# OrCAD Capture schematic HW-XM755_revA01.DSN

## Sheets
1 00_TITLE: title: HW-XM755; rev: A01; note: 038-05099-01
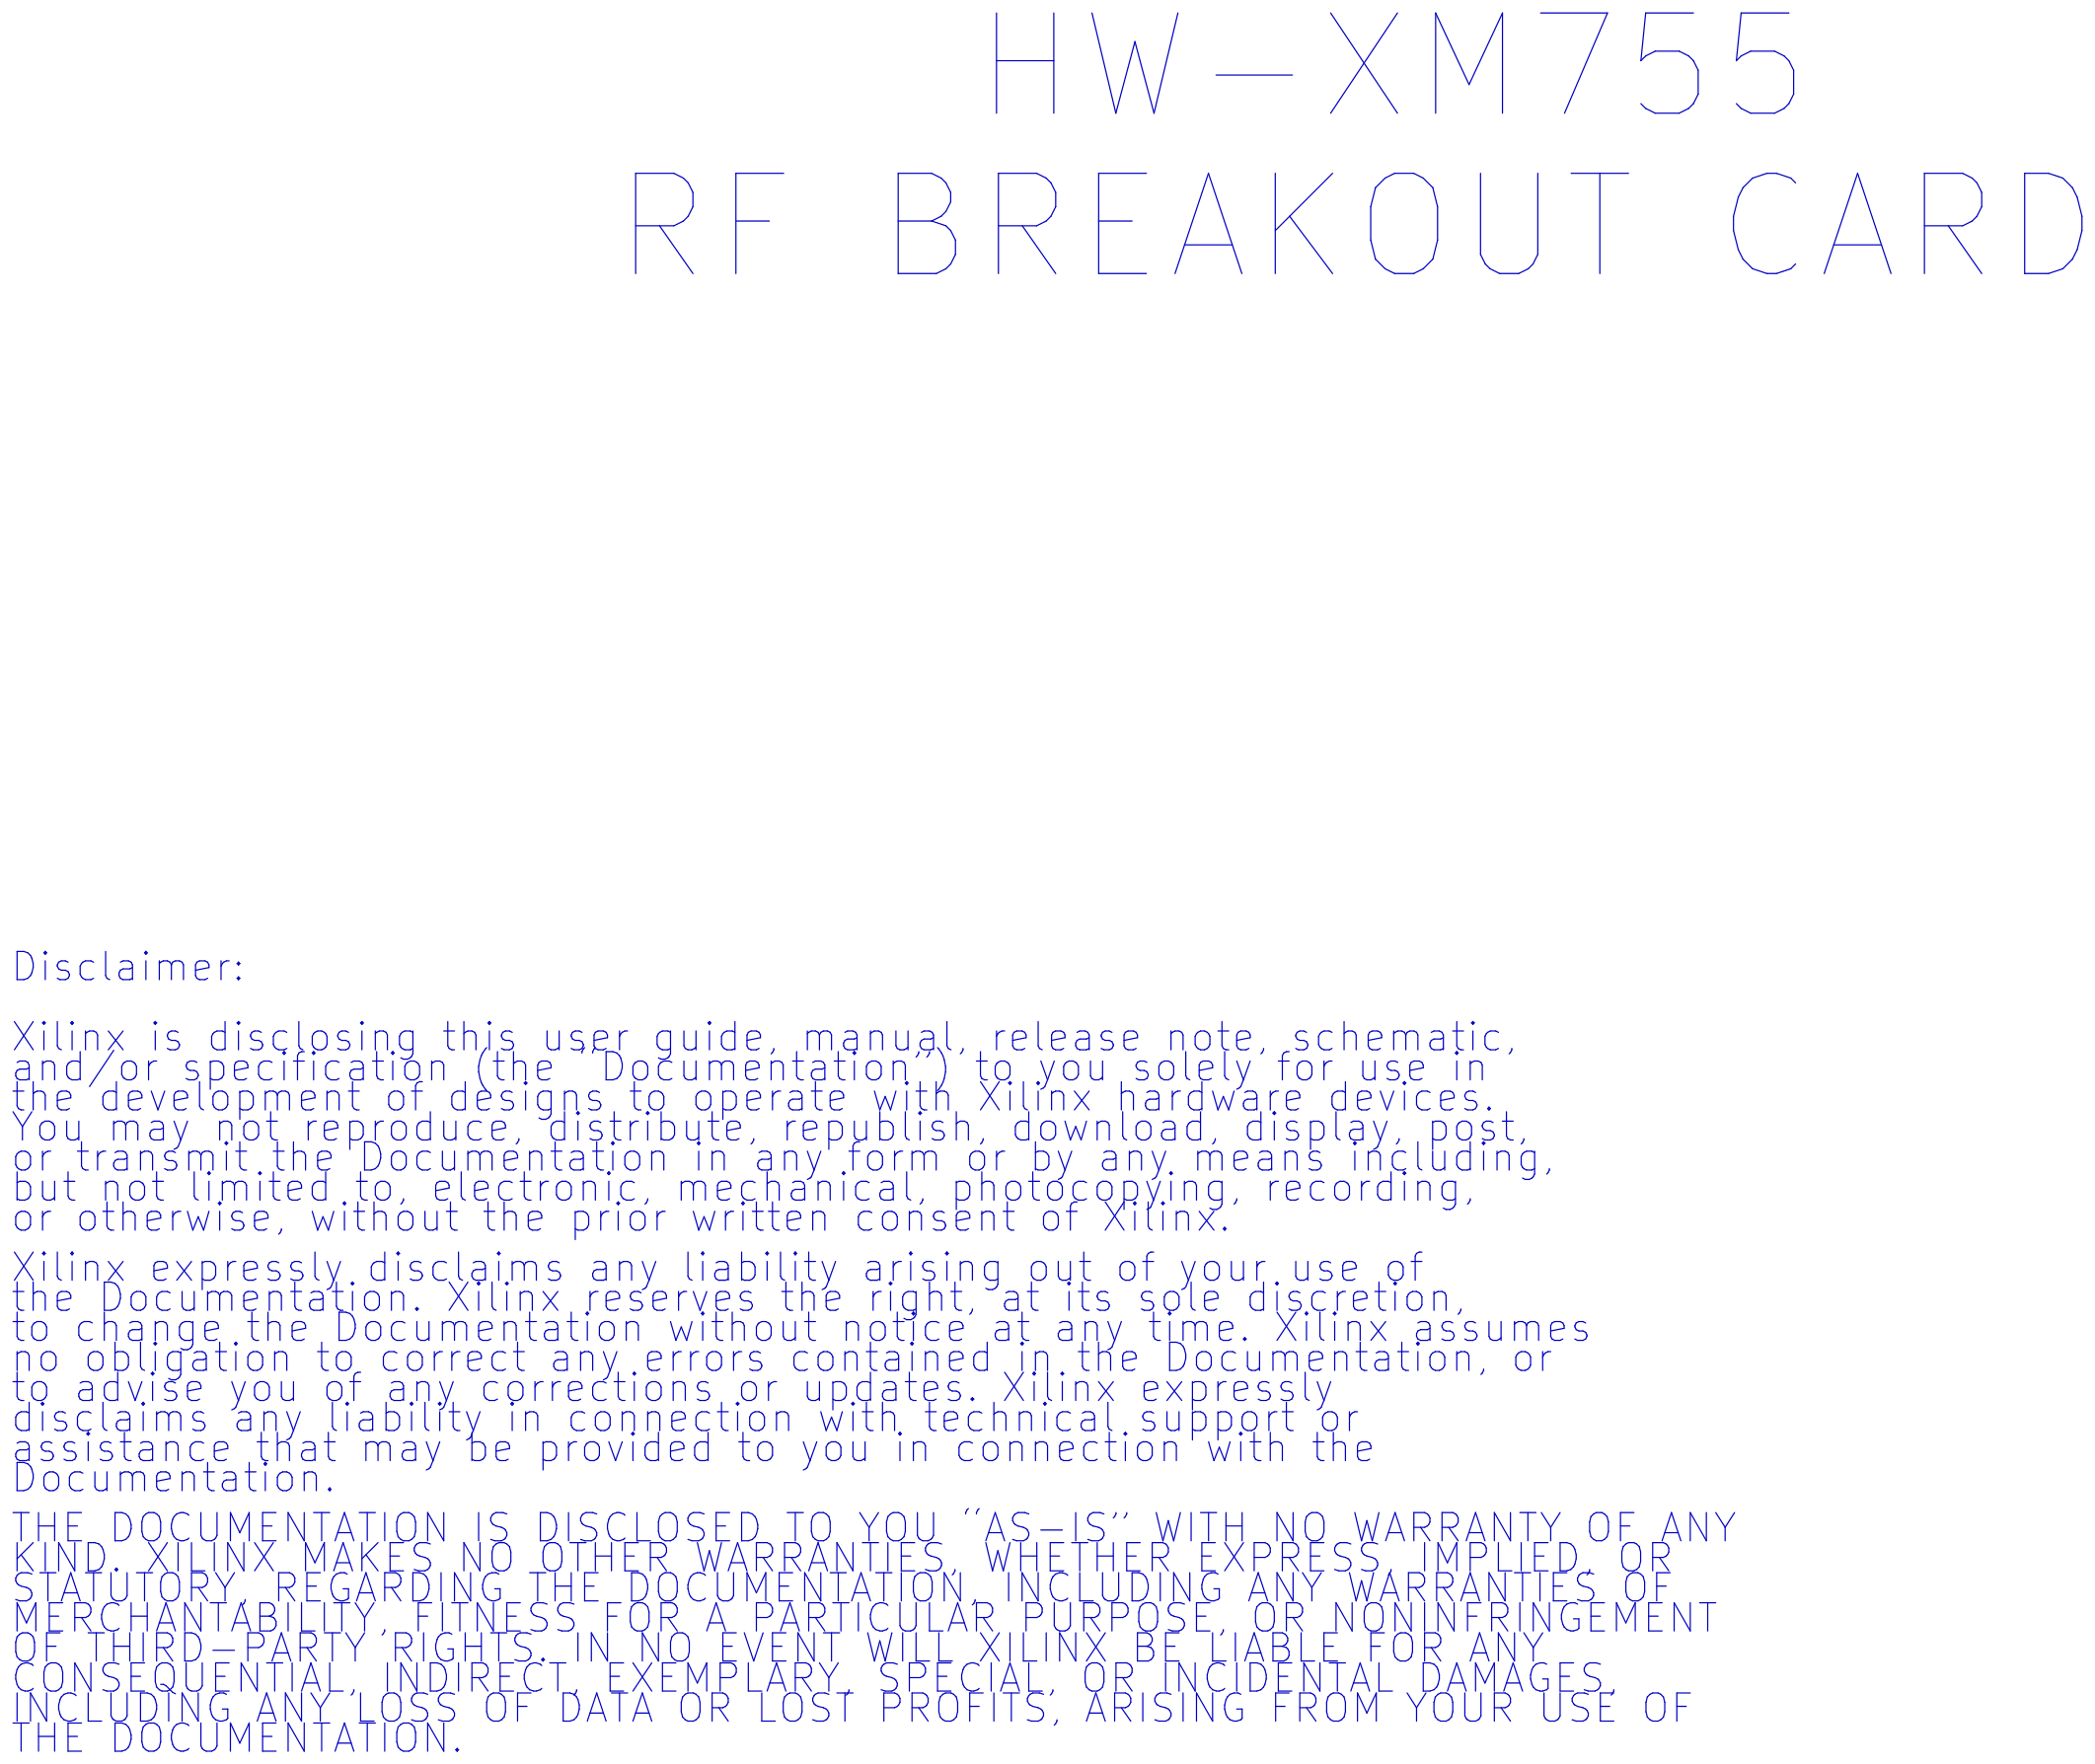
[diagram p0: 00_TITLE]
2 01_Block_Diagram
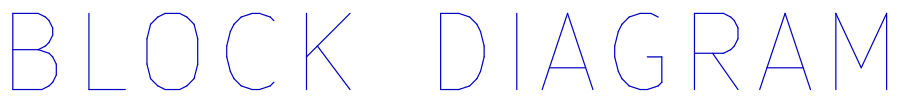
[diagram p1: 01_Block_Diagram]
3 02_Balun_ADC: size D
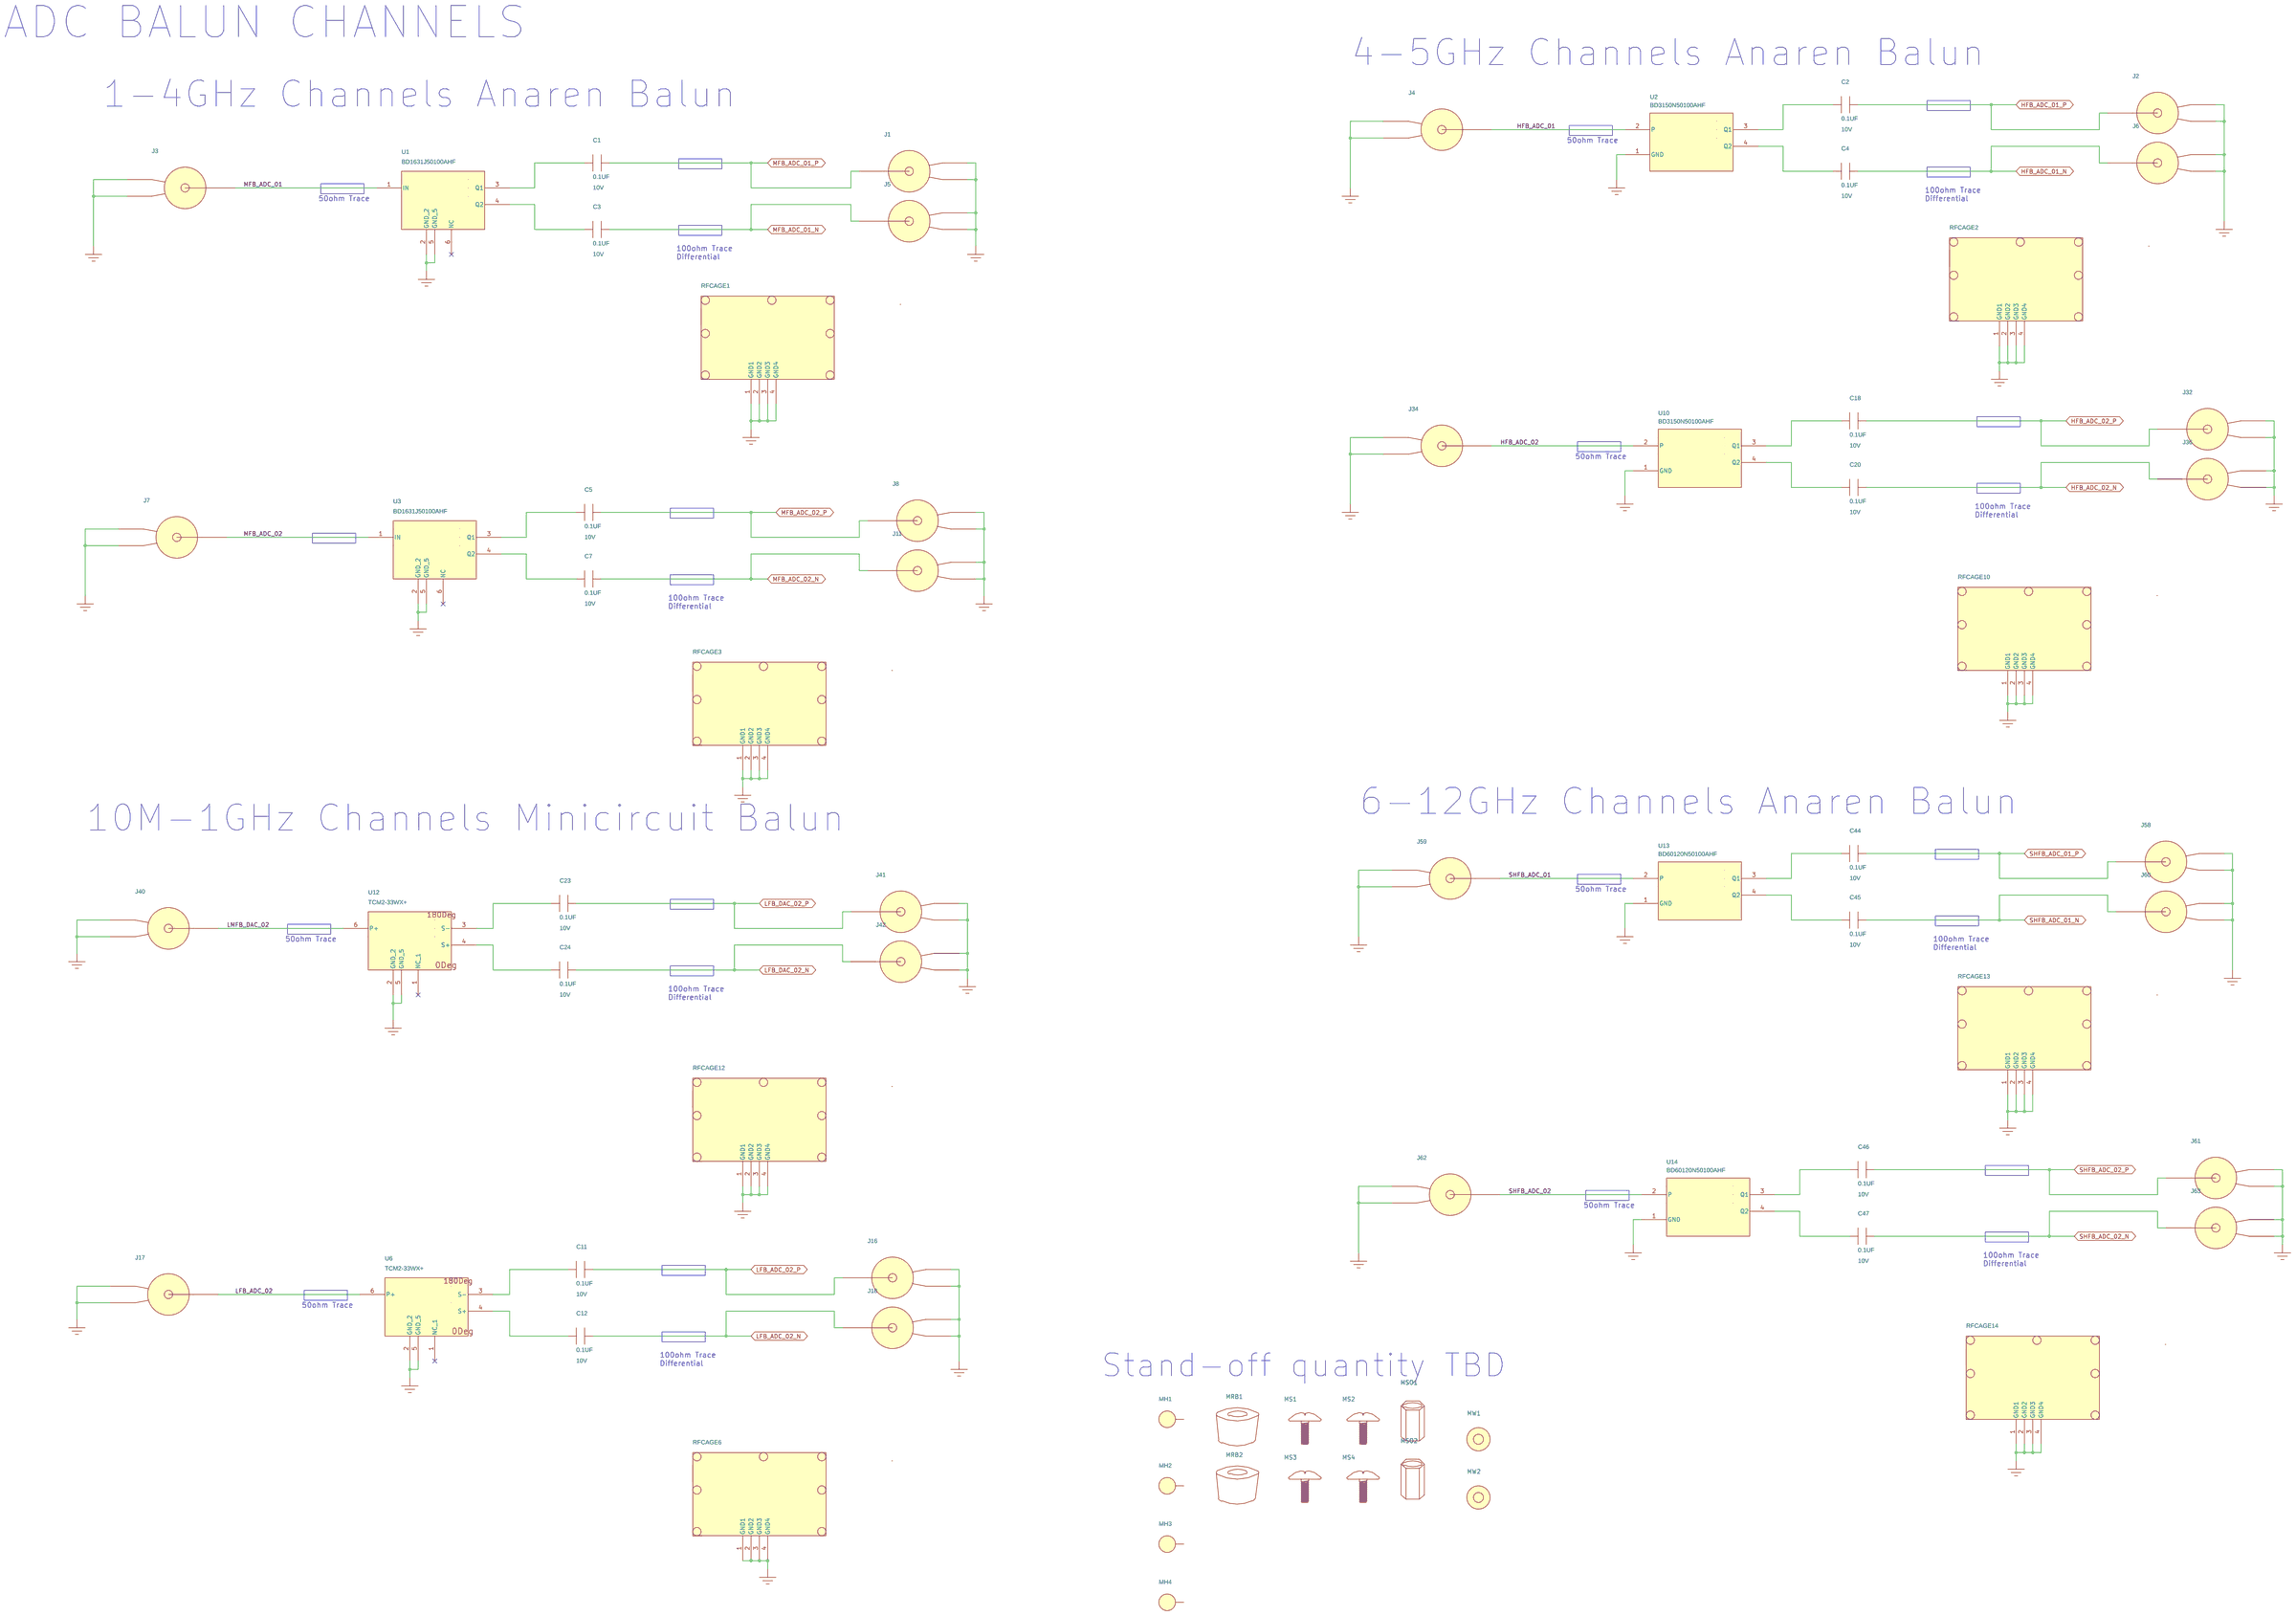
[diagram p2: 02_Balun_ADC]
4 03_SMAs_ADC: size Custom
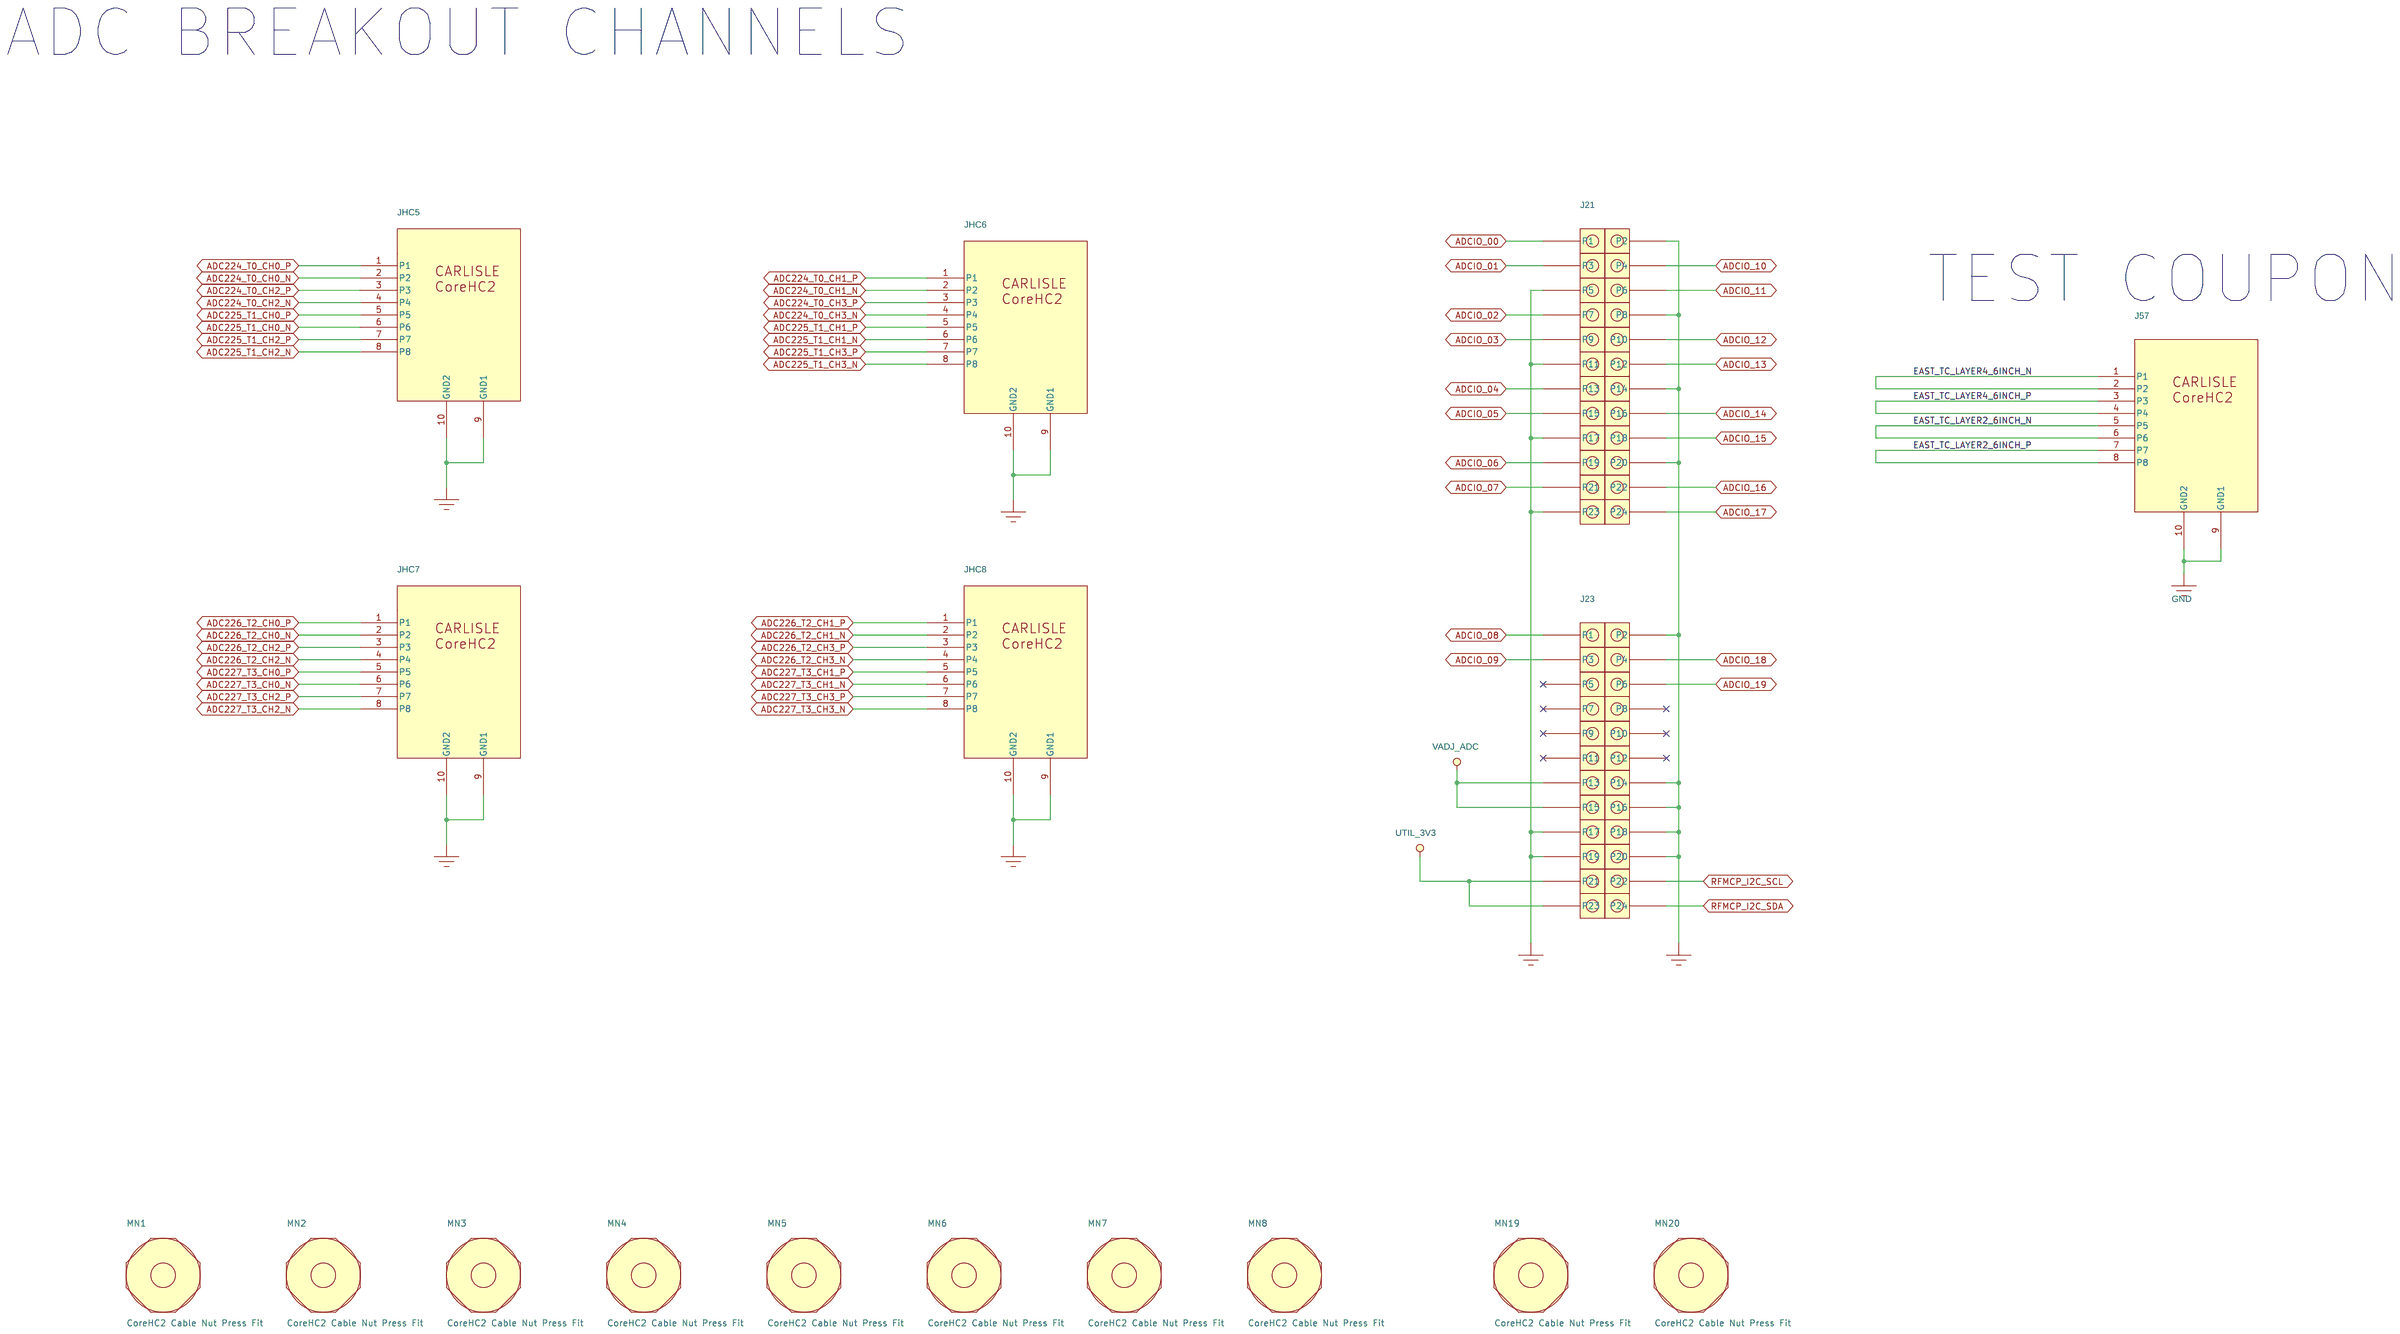
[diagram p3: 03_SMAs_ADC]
5 04_Balun_DAC: size D
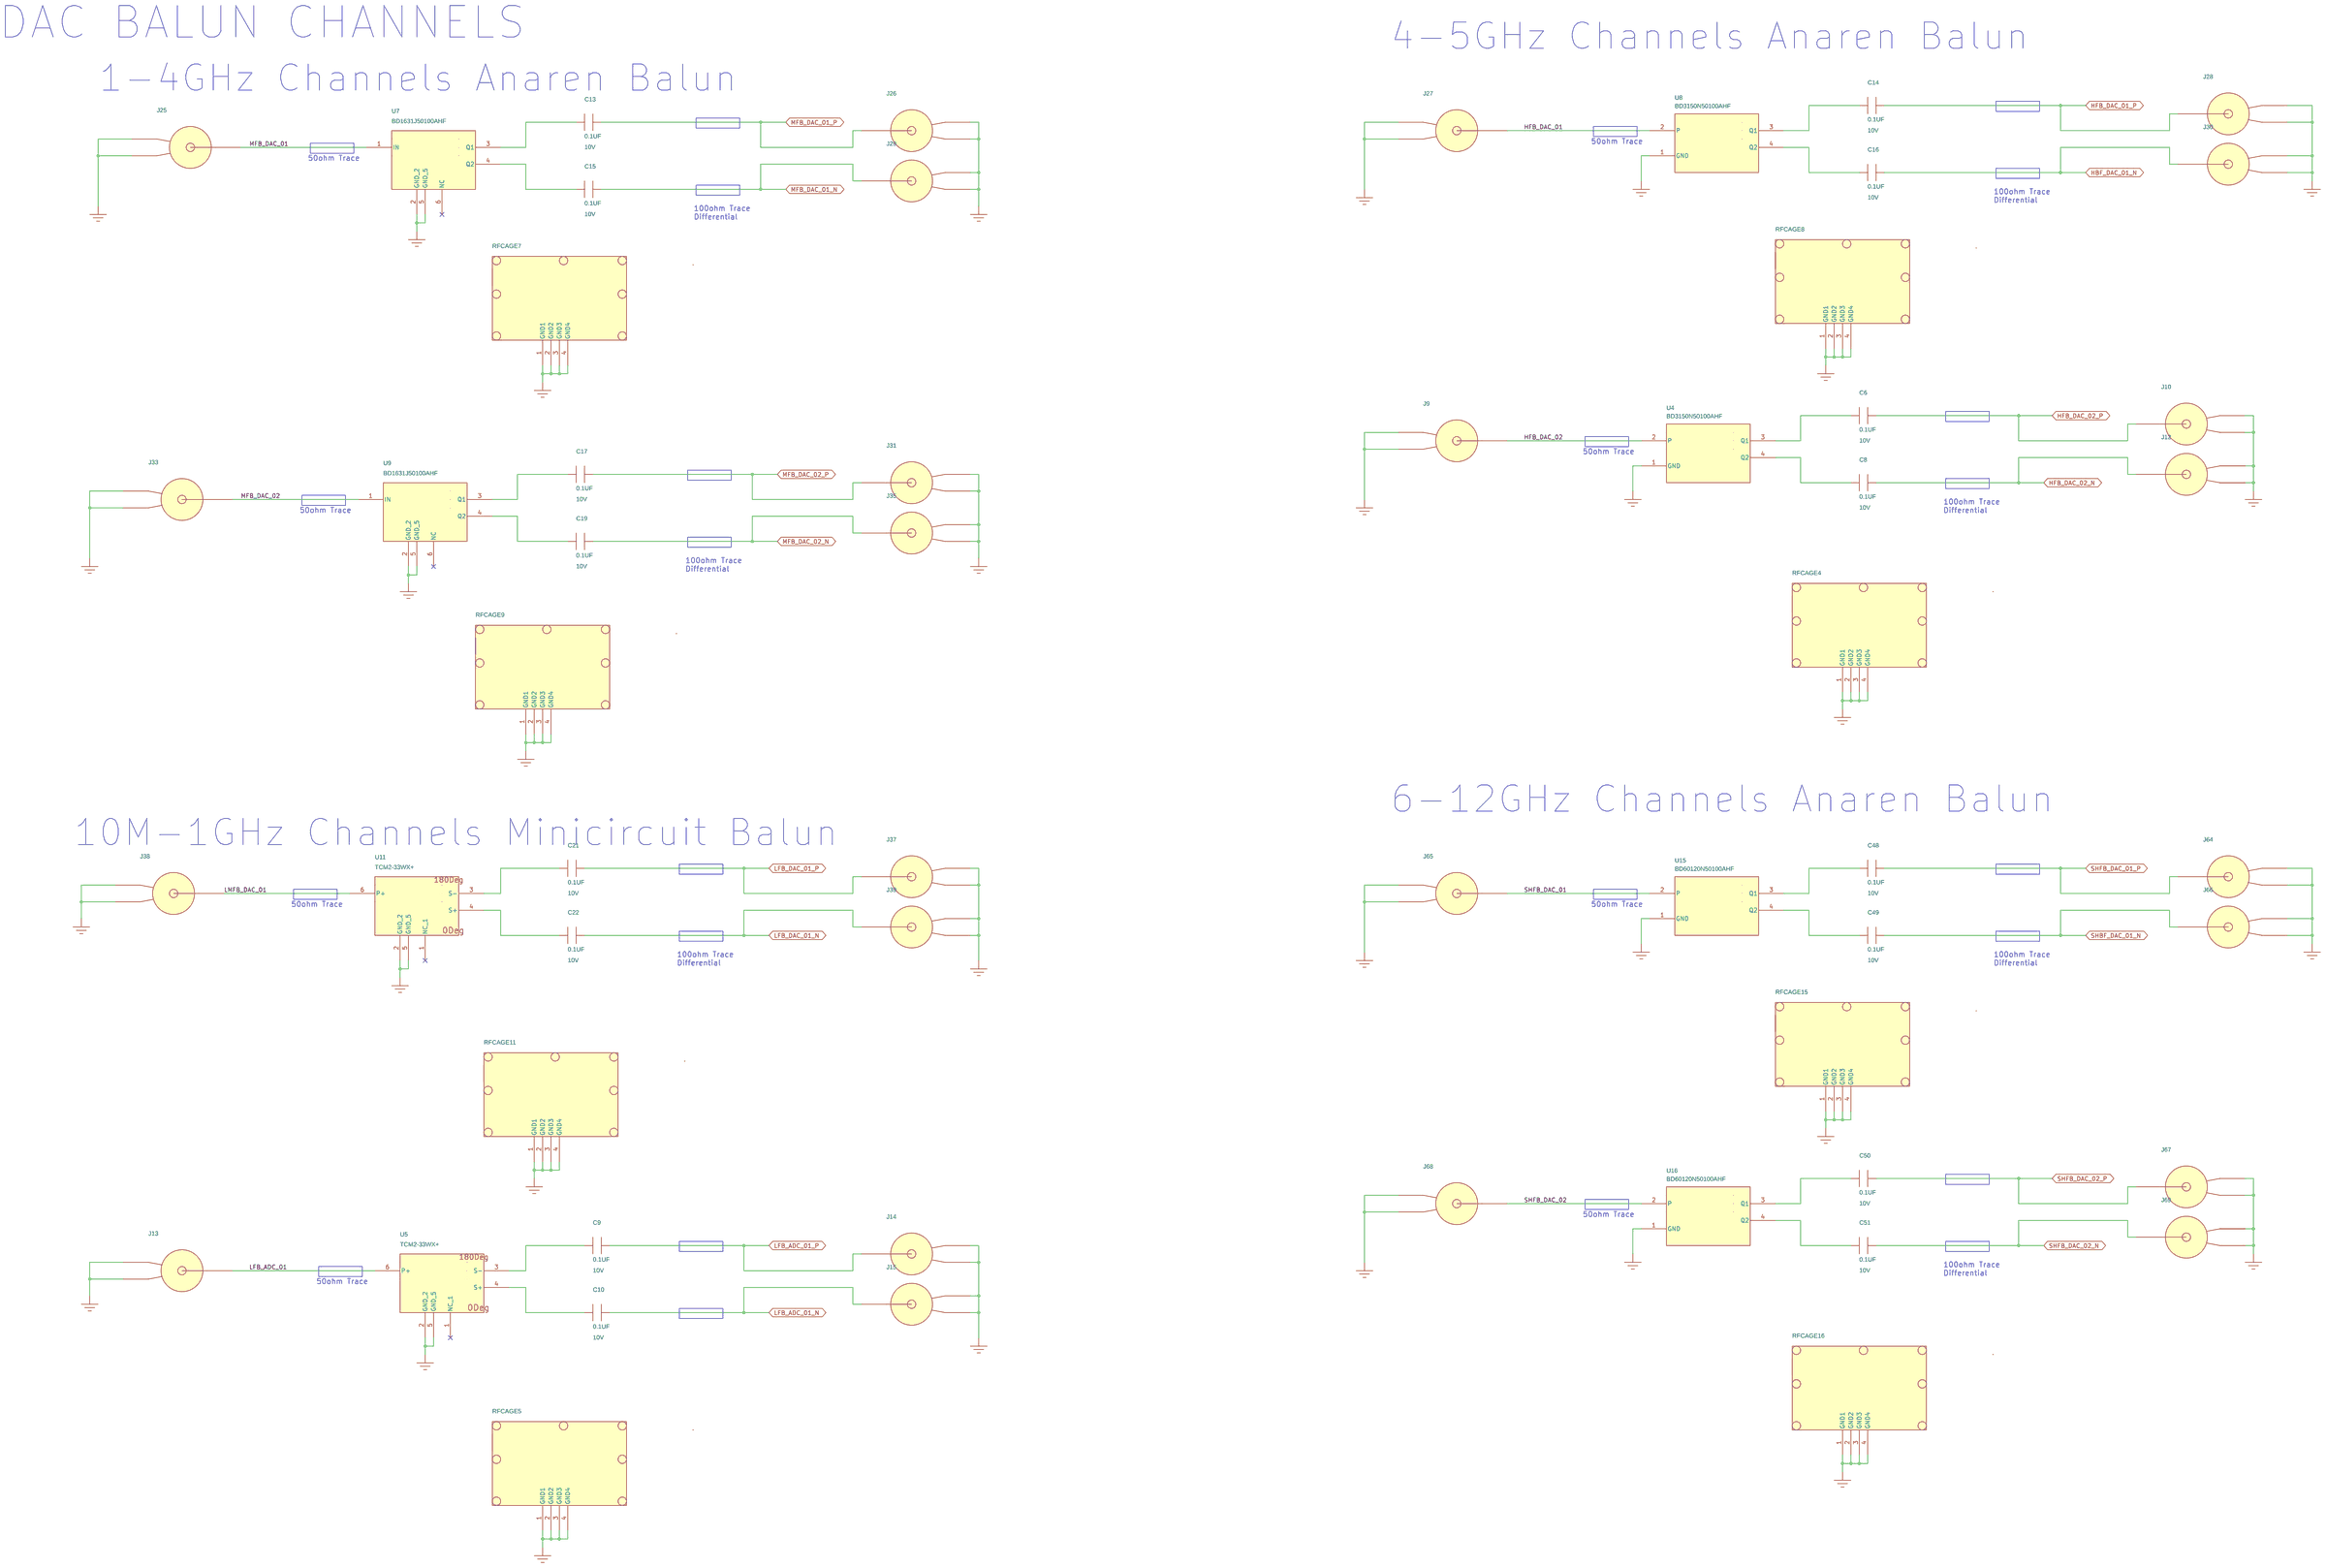
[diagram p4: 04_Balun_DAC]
6 05_SMAs_DAC: size Custom
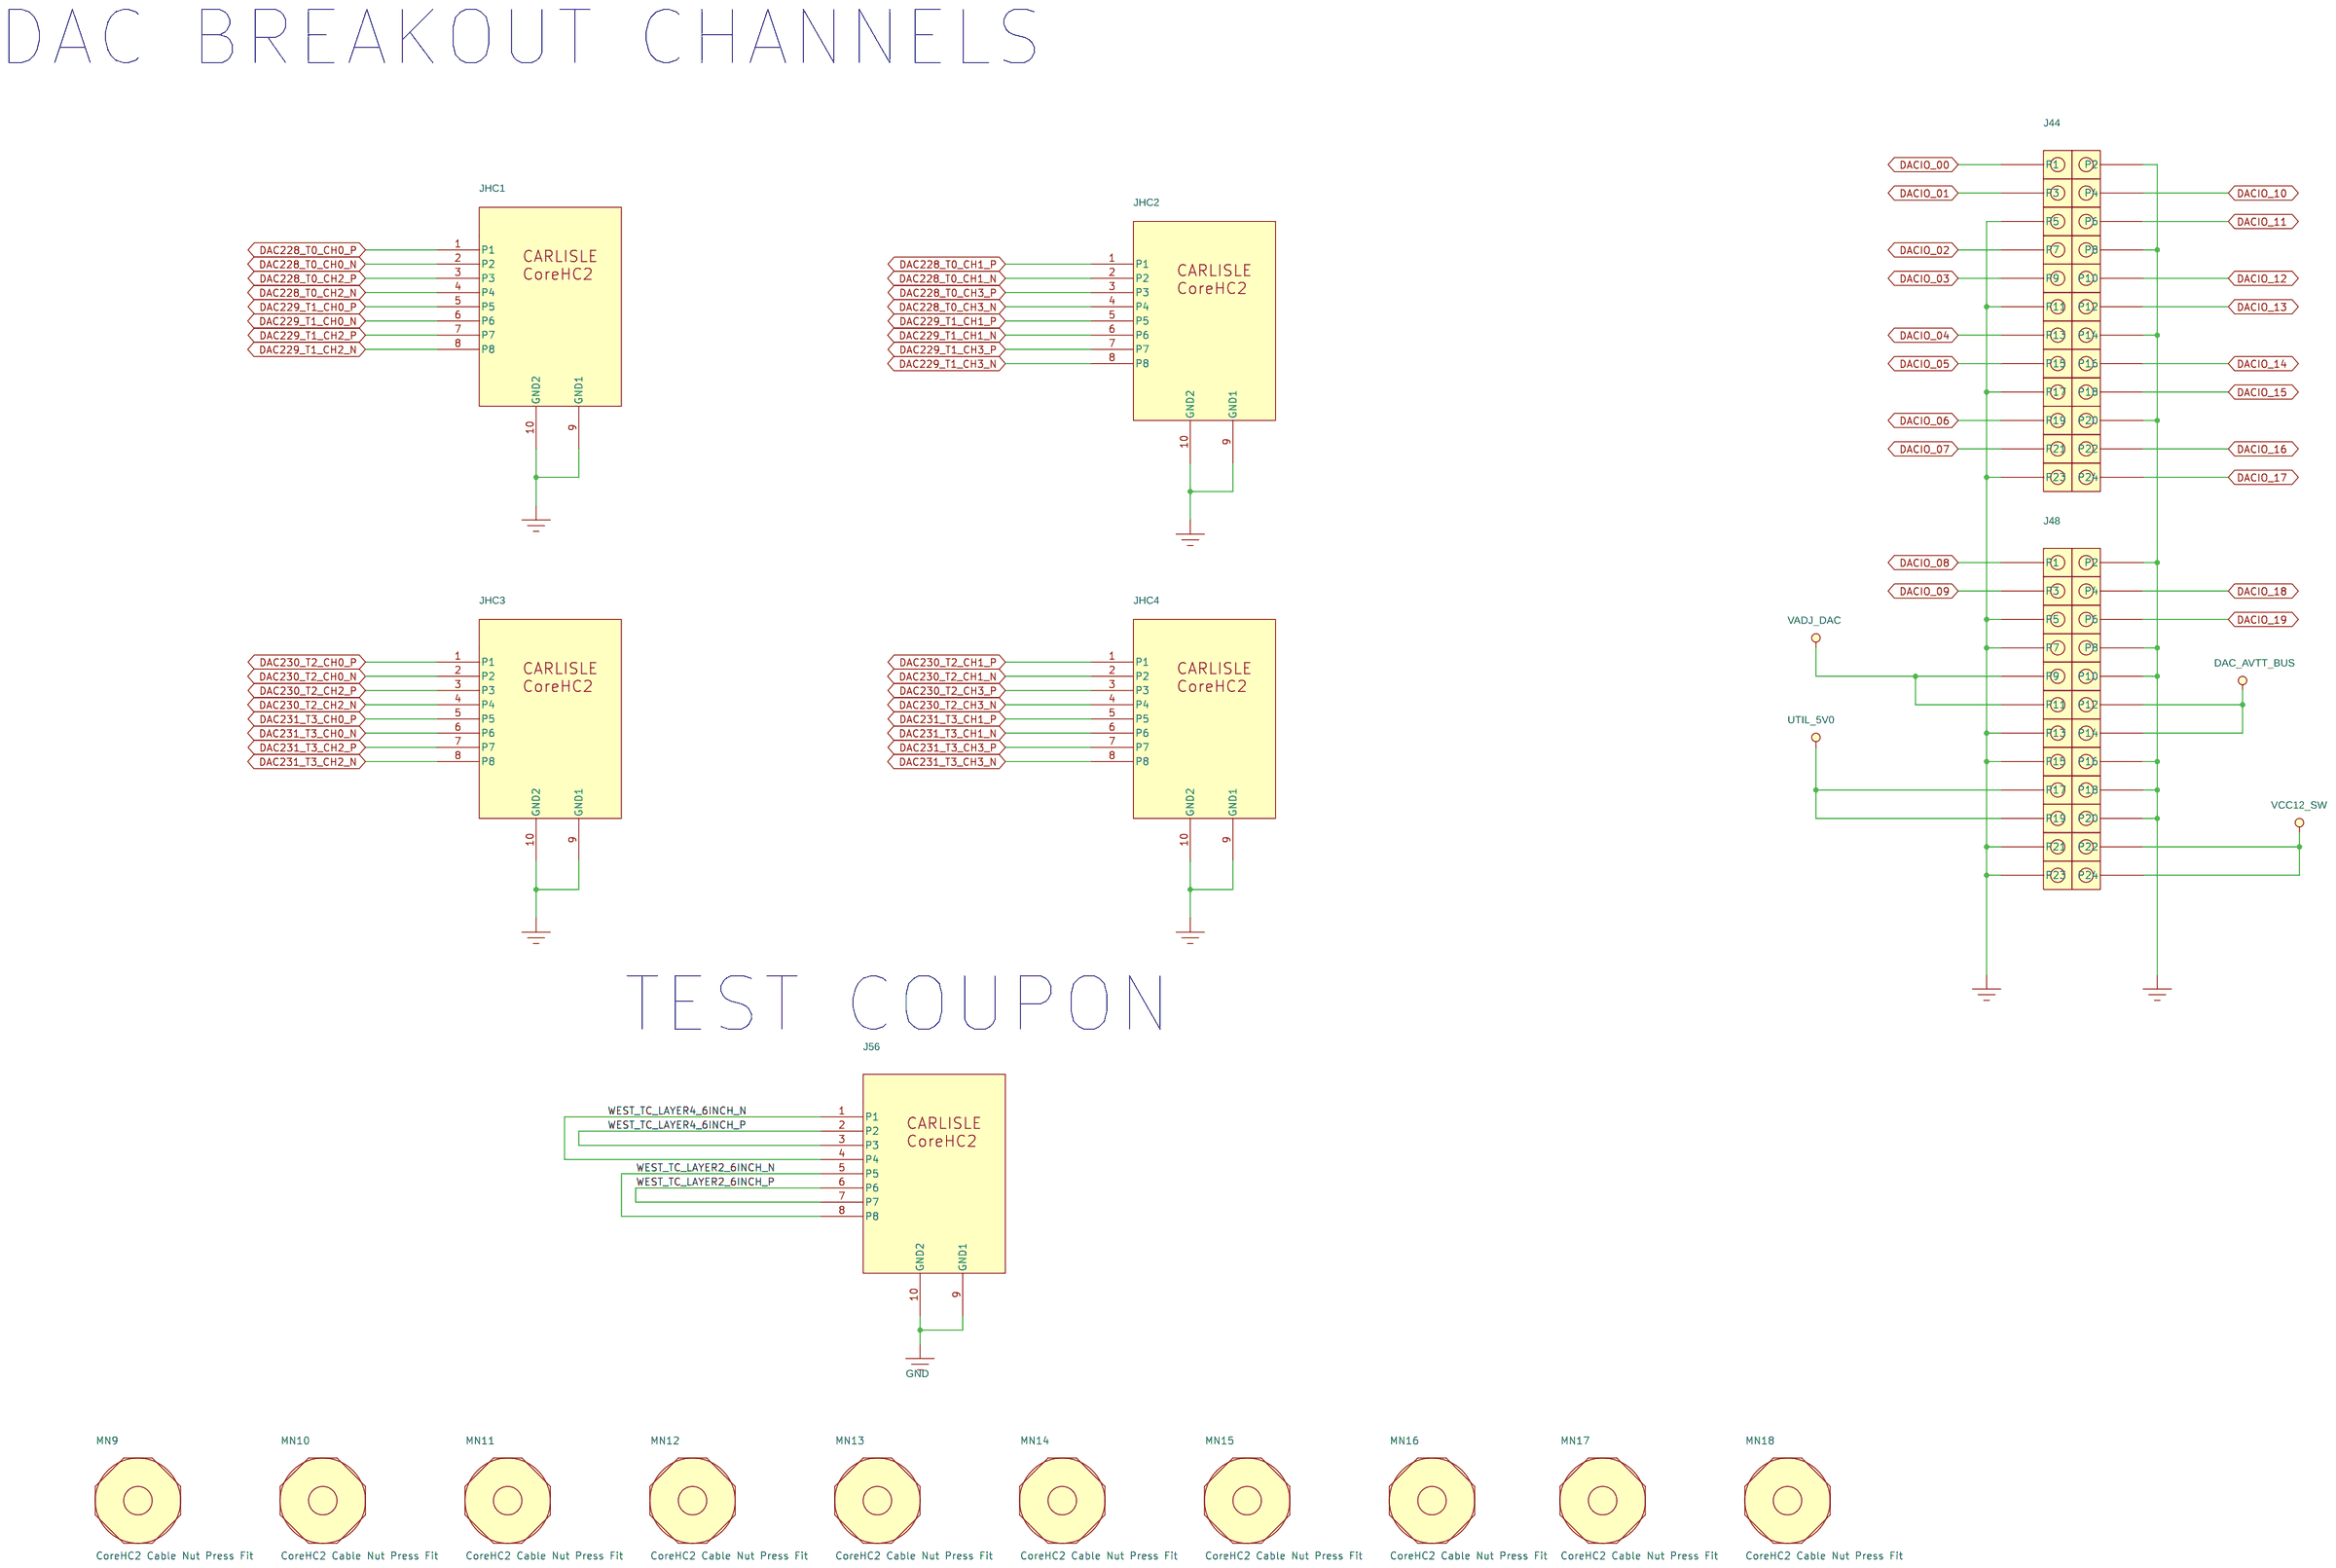
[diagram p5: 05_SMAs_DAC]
7 06_RFMC+_Connector_ADC: size Custom
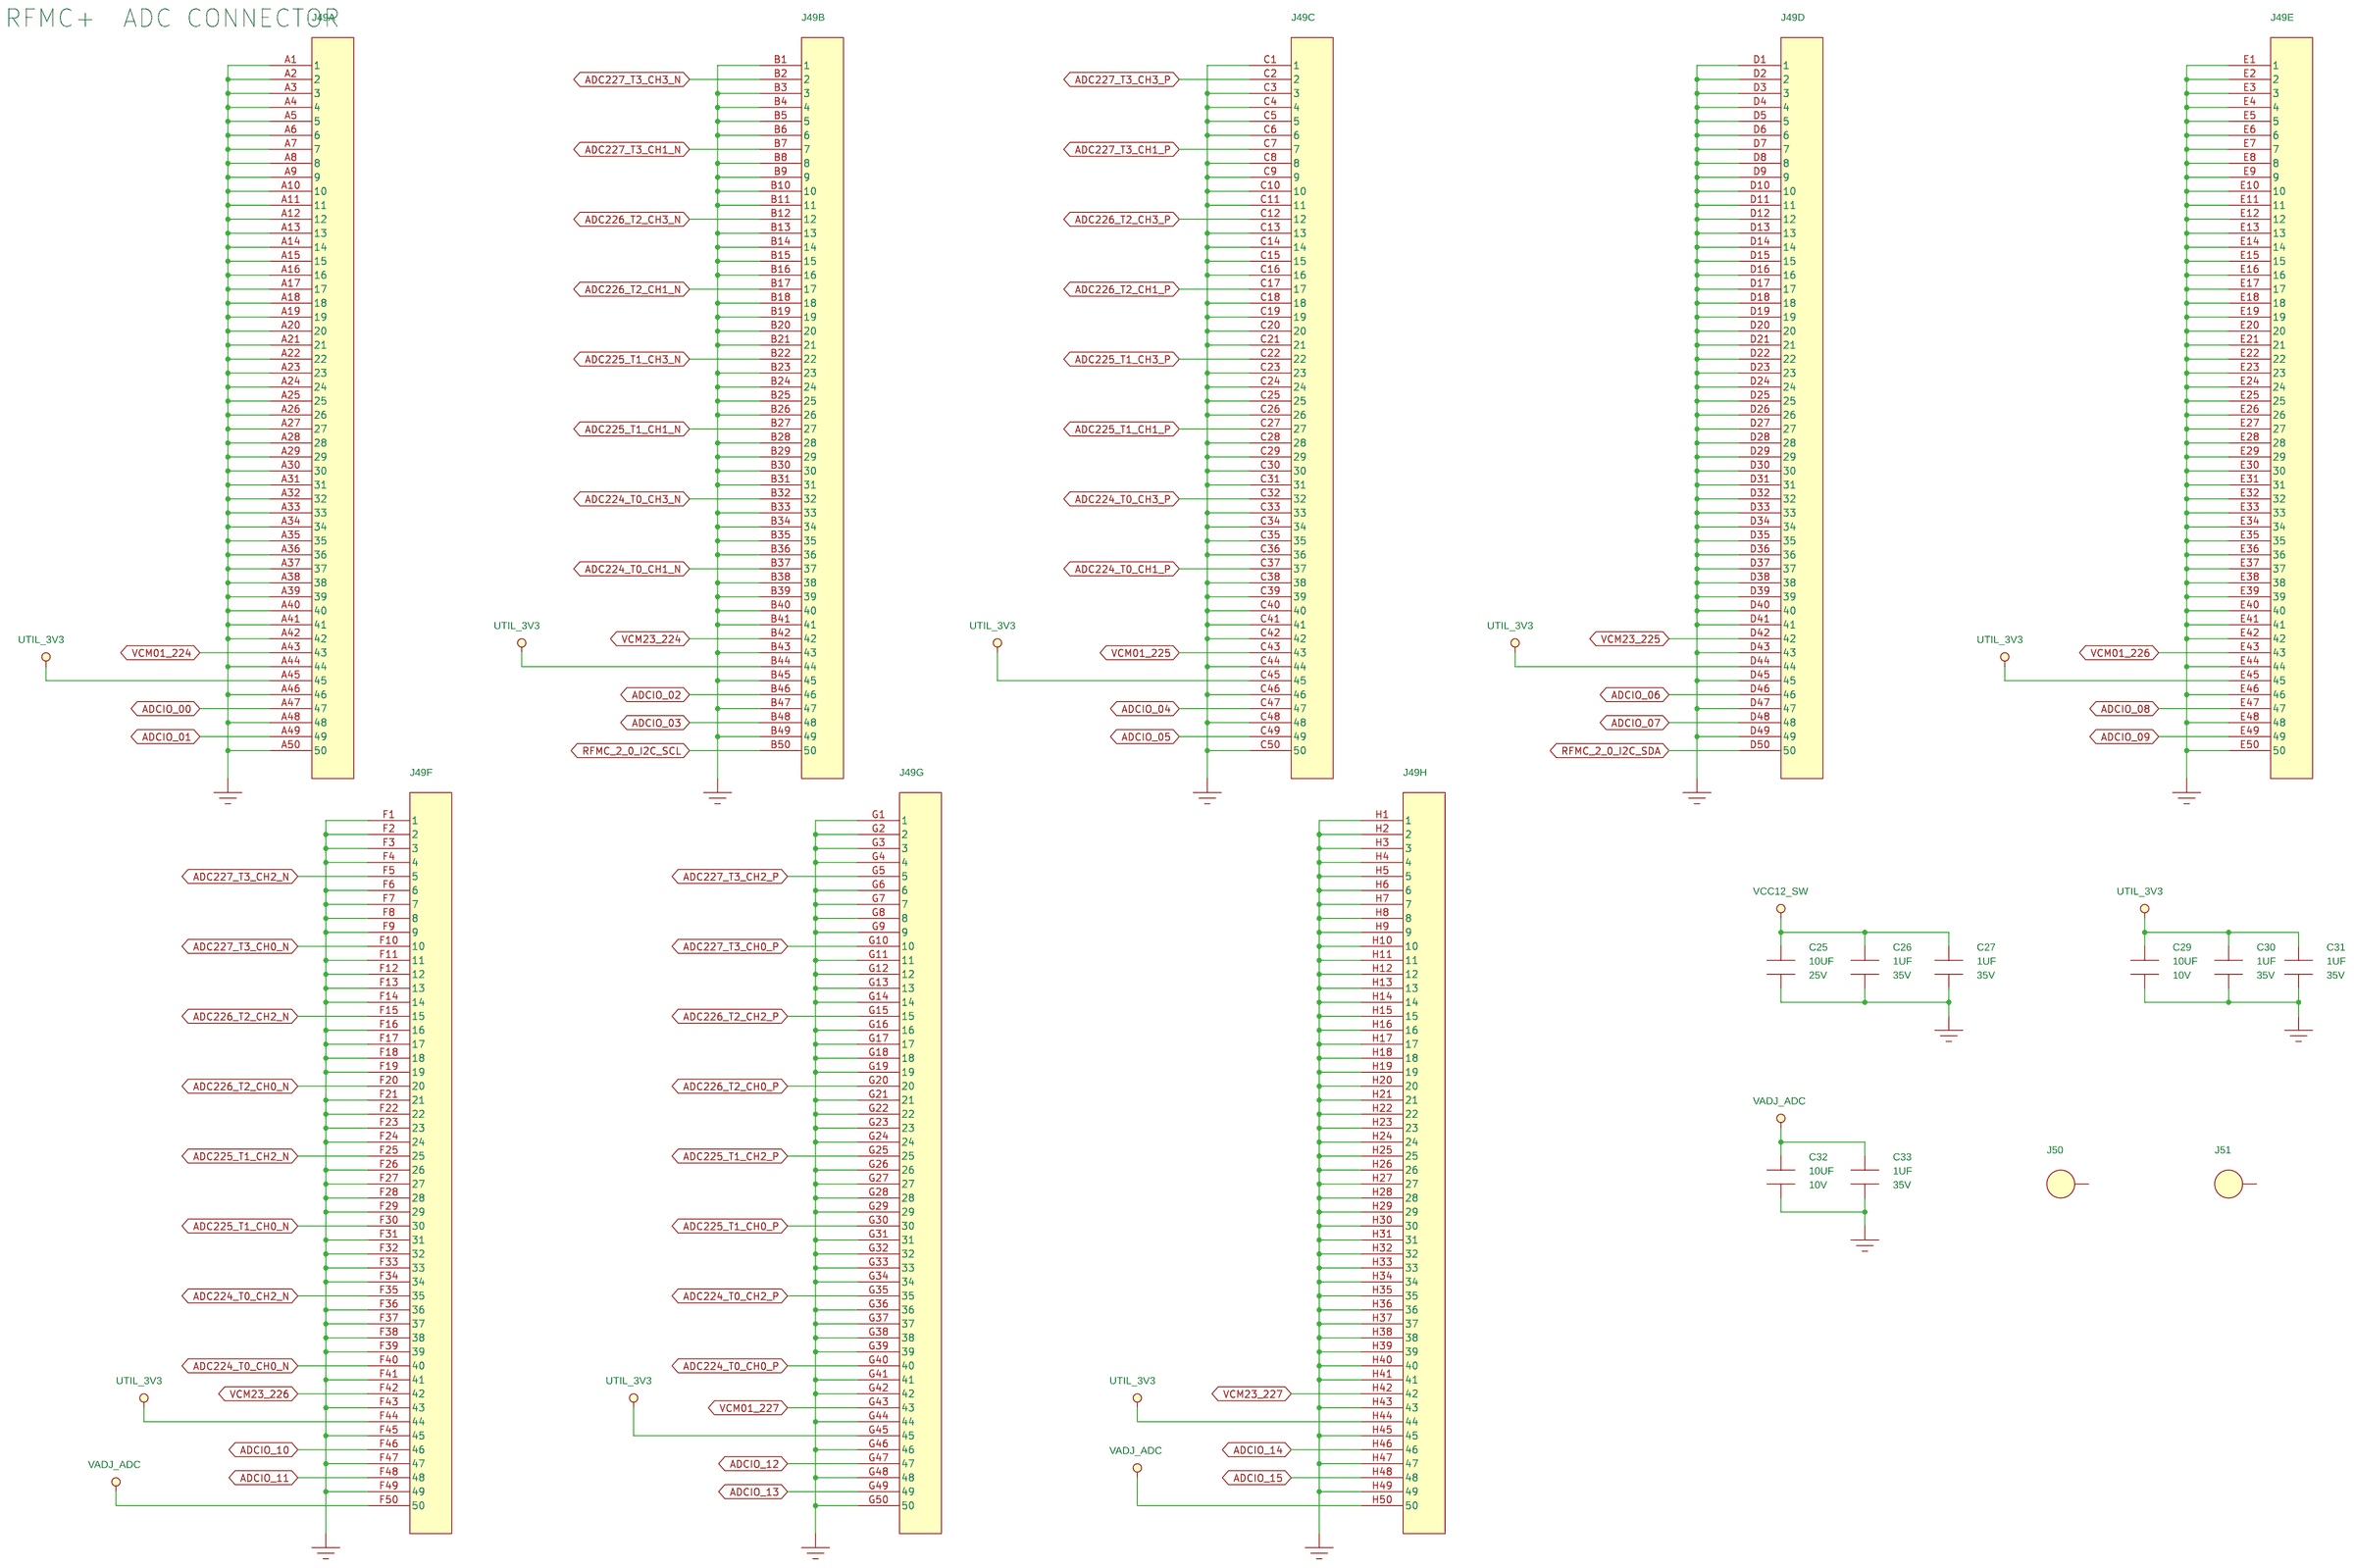
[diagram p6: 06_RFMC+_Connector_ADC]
8 07_RFMC+_Connector_DAC: size Custom
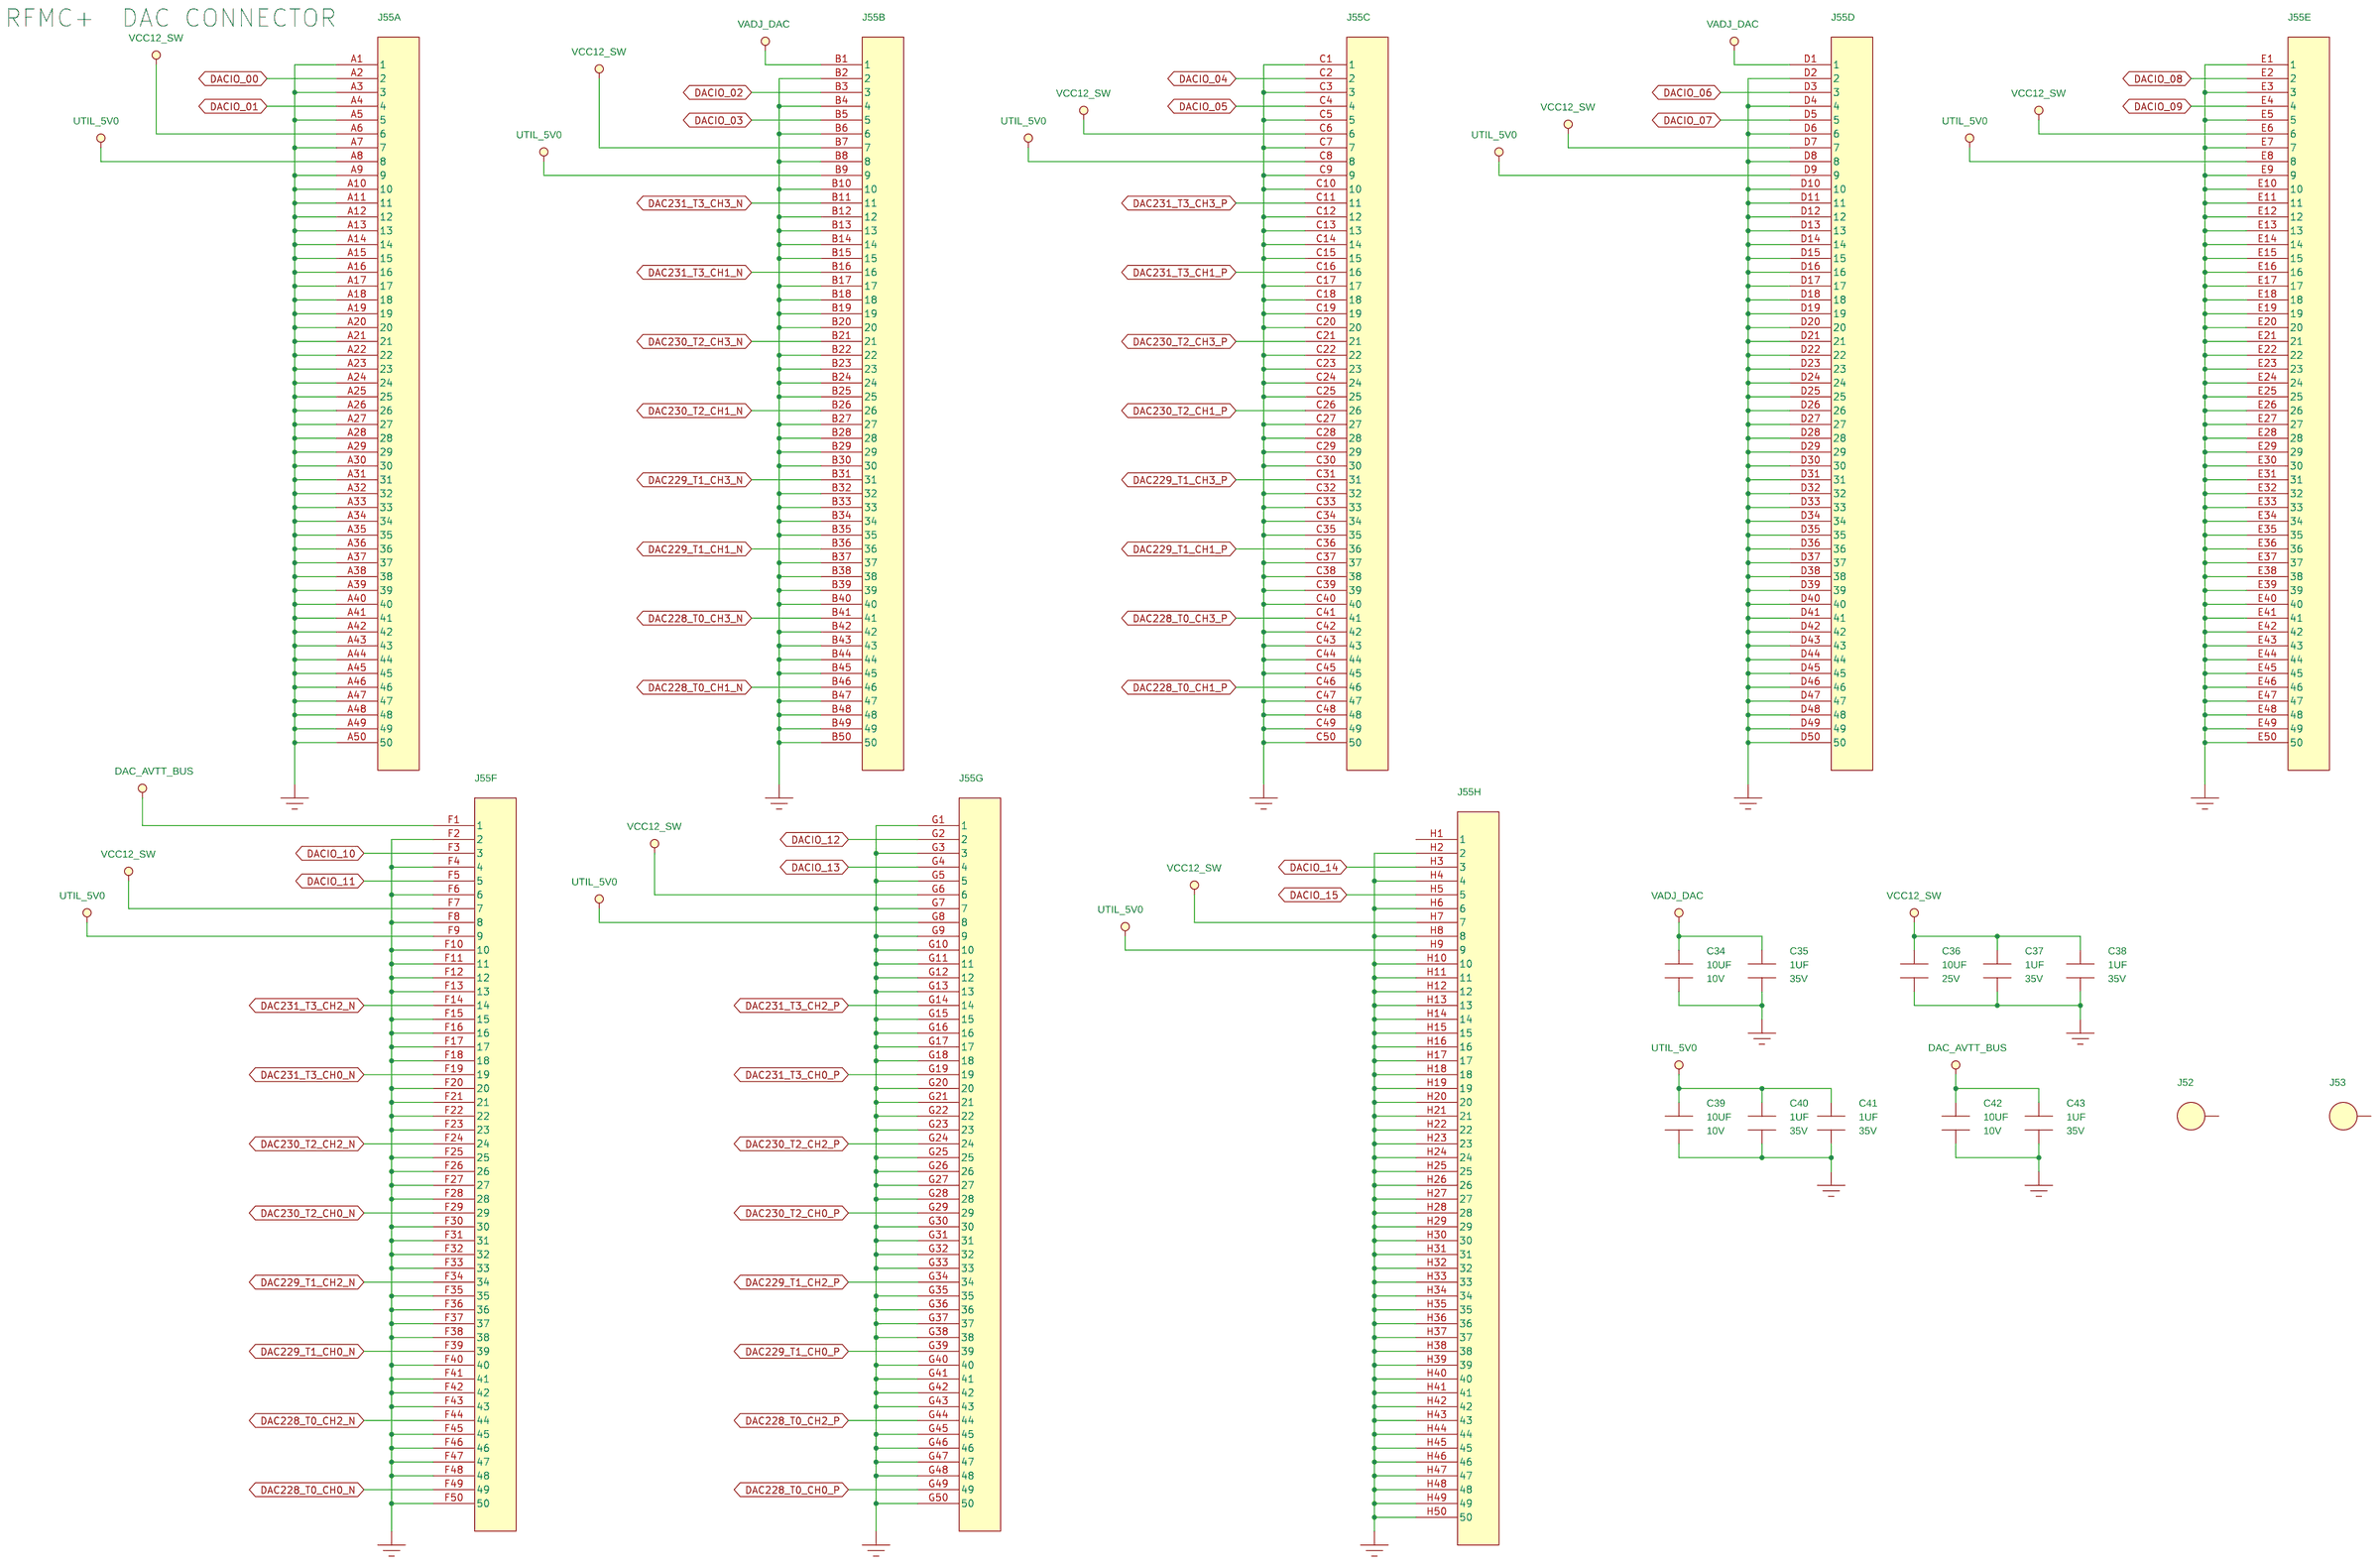
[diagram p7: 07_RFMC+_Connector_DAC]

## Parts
sheet 02_Balun_ADC
C1  0.1UF  [CAPC60X30X40]
C2  0.1UF  [CAPC60X30X40]
C3  0.1UF  [CAPC60X30X40]
C4  0.1UF  [CAPC60X30X40]
C5  0.1UF  [CAPC60X30X40]
C7  0.1UF  [CAPC60X30X40]
C11  0.1UF  [CAPC60X30X40]
C12  0.1UF  [CAPC60X30X40]
C18  0.1UF  [CAPC60X30X40]
C20  0.1UF  [CAPC60X30X40]
C23  0.1UF  [CAPC60X30X40]
C24  0.1UF  [CAPC60X30X40]
C44  0.1UF  [CAPC60X30X40]
C45  0.1UF  [CAPC60X30X40]
C46  0.1UF  [CAPC60X30X40]
C47  0.1UF  [CAPC60X30X40]
J1  CON_SMA_SCREW_ON  [SMA_3P_MOLEX_732513481]
J2  CON_SMA_SCREW_ON  [SMA_3P_MOLEX_732513481]
J3  CON_SMA_SCREW_ON  [SMA_3P_MOLEX_732513481]
J4  CON_SMA_SCREW_ON  [SMA_3P_MOLEX_732513481]
J5  CON_SMA_SCREW_ON  [SMA_3P_MOLEX_732513481]
J6  CON_SMA_SCREW_ON  [SMA_3P_MOLEX_732513481]
J7  CON_SMA_SCREW_ON  [SMA_3P_MOLEX_732513481]
J8  CON_SMA_SCREW_ON  [SMA_3P_MOLEX_732513481]
J11  CON_SMA_SCREW_ON  [SMA_3P_MOLEX_732513481]
J16  CON_SMA_SCREW_ON  [SMA_3P_MOLEX_732513481]
J17  CON_SMA_SCREW_ON  [SMA_3P_MOLEX_732513481]
J18  CON_SMA_SCREW_ON  [SMA_3P_MOLEX_732513481]
J32  CON_SMA_SCREW_ON  [SMA_3P_MOLEX_732513481]
J34  CON_SMA_SCREW_ON  [SMA_3P_MOLEX_732513481]
J36  CON_SMA_SCREW_ON  [SMA_3P_MOLEX_732513481]
J40  CON_SMA_SCREW_ON  [SMA_3P_MOLEX_732513481]
J41  CON_SMA_SCREW_ON  [SMA_3P_MOLEX_732513481]
J42  CON_SMA_SCREW_ON  [SMA_3P_MOLEX_732513481]
J58  CON_SMA_SCREW_ON  [SMA_3P_MOLEX_732513481]
J59  CON_SMA_SCREW_ON  [SMA_3P_MOLEX_732513481]
J60  CON_SMA_SCREW_ON  [SMA_3P_MOLEX_732513481]
J61  CON_SMA_SCREW_ON  [SMA_3P_MOLEX_732513481]
J62  CON_SMA_SCREW_ON  [SMA_3P_MOLEX_732513481]
J63  CON_SMA_SCREW_ON  [SMA_3P_MOLEX_732513481]
MH1  MH_150_250  [MH_250H150]
MH2  MH_150_250  [MH_250H150]
MH3  MH_150_250  [MH_250H150]
MH4  MH_150_250  [MH_250H150]
MRB1  RUBBER_BUMPER
MRB2  RUBBER_BUMPER
MS1  MACHINE_SCREW_4-40
MS2  MACHINE_SCREW_4-40
MS3  MACHINE_SCREW_4-40
MS4  MACHINE_SCREW_4-40
MSO1  STANDOFF_0P625
MSO2  STANDOFF_0P625
MW1  WASHER_FLAT_4
MW2  WASHER_FLAT_4
RFCAGE1  EMI CAGE LT-8388  [LT-7925]
RFCAGE2  EMI CAGE LT-8388  [LT-7925]
RFCAGE3  EMI CAGE LT-8388  [LT-7925]
RFCAGE6  EMI CAGE LT-8388  [LT-7925]
RFCAGE10  EMI CAGE LT-8388  [LT-7925]
RFCAGE12  EMI CAGE LT-8388  [LT-7925]
RFCAGE13  EMI CAGE LT-8388  [LT-7925]
RFCAGE14  EMI CAGE LT-8388  [LT-7925]
U1  BD1631J50100AHF  [BALUN_0805]
U2  BD3150N50100AHF  [BD3150N50100AHF]
U3  BD1631J50100AHF  [BALUN_0805]
U6  TCM2-33WX+  [TRANS_DB1627]
U10  BD3150N50100AHF  [BD3150N50100AHF]
U12  TCM2-33WX+  [TRANS_DB1627]
U13  BD60120N50100AHF  [BD60120N50100AHF]
U14  BD60120N50100AHF  [BD60120N50100AHF]
sheet 03_SMAs_ADC
J21  HDR_2X12  [HDR_2X12]
J23  HDR_2X12  [HDR_2X12]
J57  COREHC2_8CH  [CON_CARLISE_COREH2C_8P]
JHC5  COREHC2_8CH  [CON_CARLISE_COREH2C_8P]
JHC6  COREHC2_8CH  [CON_CARLISE_COREH2C_8P]
JHC7  COREHC2_8CH  [CON_CARLISE_COREH2C_8P]
JHC8  COREHC2_8CH  [CON_CARLISE_COREH2C_8P]
MN1  CoreHC2 Cable Nut Press Fit
MN2  CoreHC2 Cable Nut Press Fit
MN3  CoreHC2 Cable Nut Press Fit
MN4  CoreHC2 Cable Nut Press Fit
MN5  CoreHC2 Cable Nut Press Fit
MN6  CoreHC2 Cable Nut Press Fit
MN7  CoreHC2 Cable Nut Press Fit
MN8  CoreHC2 Cable Nut Press Fit
MN19  CoreHC2 Cable Nut Press Fit
MN20  CoreHC2 Cable Nut Press Fit
sheet 04_Balun_DAC
C6  0.1UF  [CAPC60X30X40]
C8  0.1UF  [CAPC60X30X40]
C9  0.1UF  [CAPC60X30X40]
C10  0.1UF  [CAPC60X30X40]
C13  0.1UF  [CAPC60X30X40]
C14  0.1UF  [CAPC60X30X40]
C15  0.1UF  [CAPC60X30X40]
C16  0.1UF  [CAPC60X30X40]
C17  0.1UF  [CAPC60X30X40]
C19  0.1UF  [CAPC60X30X40]
C21  0.1UF  [CAPC60X30X40]
C22  0.1UF  [CAPC60X30X40]
C48  0.1UF  [CAPC60X30X40]
C49  0.1UF  [CAPC60X30X40]
C50  0.1UF  [CAPC60X30X40]
C51  0.1UF  [CAPC60X30X40]
J9  CON_SMA_SCREW_ON  [SMA_3P_MOLEX_732513481]
J10  CON_SMA_SCREW_ON  [SMA_3P_MOLEX_732513481]
J12  CON_SMA_SCREW_ON  [SMA_3P_MOLEX_732513481]
J13  CON_SMA_SCREW_ON  [SMA_3P_MOLEX_732513481]
J14  CON_SMA_SCREW_ON  [SMA_3P_MOLEX_732513481]
J15  CON_SMA_SCREW_ON  [SMA_3P_MOLEX_732513481]
J25  CON_SMA_SCREW_ON  [SMA_3P_MOLEX_732513481]
J26  CON_SMA_SCREW_ON  [SMA_3P_MOLEX_732513481]
J27  CON_SMA_SCREW_ON  [SMA_3P_MOLEX_732513481]
J28  CON_SMA_SCREW_ON  [SMA_3P_MOLEX_732513481]
J29  CON_SMA_SCREW_ON  [SMA_3P_MOLEX_732513481]
J30  CON_SMA_SCREW_ON  [SMA_3P_MOLEX_732513481]
J31  CON_SMA_SCREW_ON  [SMA_3P_MOLEX_732513481]
J33  CON_SMA_SCREW_ON  [SMA_3P_MOLEX_732513481]
J35  CON_SMA_SCREW_ON  [SMA_3P_MOLEX_732513481]
J37  CON_SMA_SCREW_ON  [SMA_3P_MOLEX_732513481]
J38  CON_SMA_SCREW_ON  [SMA_3P_MOLEX_732513481]
J39  CON_SMA_SCREW_ON  [SMA_3P_MOLEX_732513481]
J64  CON_SMA_SCREW_ON  [SMA_3P_MOLEX_732513481]
J65  CON_SMA_SCREW_ON  [SMA_3P_MOLEX_732513481]
J66  CON_SMA_SCREW_ON  [SMA_3P_MOLEX_732513481]
J67  CON_SMA_SCREW_ON  [SMA_3P_MOLEX_732513481]
J68  CON_SMA_SCREW_ON  [SMA_3P_MOLEX_732513481]
J69  CON_SMA_SCREW_ON  [SMA_3P_MOLEX_732513481]
RFCAGE4  EMI CAGE LT-8388  [LT-7925]
RFCAGE5  EMI CAGE LT-8388  [LT-7925]
RFCAGE7  EMI CAGE LT-8388  [LT-7925]
RFCAGE8  EMI CAGE LT-8388  [LT-7925]
RFCAGE9  EMI CAGE LT-8388  [LT-7925]
RFCAGE11  EMI CAGE LT-8388  [LT-7925]
RFCAGE15  EMI CAGE LT-8388  [LT-7925]
RFCAGE16  EMI CAGE LT-8388  [LT-7925]
U4  BD3150N50100AHF  [BD3150N50100AHF]
U5  TCM2-33WX+  [TRANS_DB1627]
U7  BD1631J50100AHF  [BALUN_0805]
U8  BD3150N50100AHF  [BD3150N50100AHF]
U9  BD1631J50100AHF  [BALUN_0805]
U11  TCM2-33WX+  [TRANS_DB1627]
U15  BD60120N50100AHF  [BD60120N50100AHF]
U16  BD60120N50100AHF  [BD60120N50100AHF]
sheet 05_SMAs_DAC
J44  HDR_2X12  [HDR_2X12]
J48  HDR_2X12  [HDR_2X12]
J56  COREHC2_8CH  [CON_CARLISE_COREH2C_8P]
JHC1  COREHC2_8CH  [CON_CARLISE_COREH2C_8P]
JHC2  COREHC2_8CH  [CON_CARLISE_COREH2C_8P]
JHC3  COREHC2_8CH  [CON_CARLISE_COREH2C_8P]
JHC4  COREHC2_8CH  [CON_CARLISE_COREH2C_8P]
MN9  CoreHC2 Cable Nut Press Fit
MN10  CoreHC2 Cable Nut Press Fit
MN11  CoreHC2 Cable Nut Press Fit
MN12  CoreHC2 Cable Nut Press Fit
MN13  CoreHC2 Cable Nut Press Fit
MN14  CoreHC2 Cable Nut Press Fit
MN15  CoreHC2 Cable Nut Press Fit
MN16  CoreHC2 Cable Nut Press Fit
MN17  CoreHC2 Cable Nut Press Fit
MN18  CoreHC2 Cable Nut Press Fit
sheet 06_RFMC+_Connector_ADC
C25  10UF  [CAPC320X250X220]
C26  1UF  [CAPC100X50X60]
C27  1UF  [CAPC100X50X60]
C29  10UF  [CAPC200X125X155]
C30  1UF  [CAPC100X50X60]
C31  1UF  [CAPC100X50X60]
C32  10UF  [CAPC200X125X155]
C33  1UF  [CAPC100X50X60]
J49  LPAM-50-01.0-L-08-2-K-TR  [SAMTEC_LPAM_50_030_L_08_2_K_TR]  (sections A,B,C,D,E,F,G,H)
J50  JSO_0415_01_PRESS_FIT  [JSO_0415_01_PRESS_FIT]
J51  JSO_0415_01_PRESS_FIT  [JSO_0415_01_PRESS_FIT]
sheet 07_RFMC+_Connector_DAC
C34  10UF  [CAPC200X125X155]
C35  1UF  [CAPC100X50X60]
C36  10UF  [CAPC320X250X220]
C37  1UF  [CAPC100X50X60]
C38  1UF  [CAPC100X50X60]
C39  10UF  [CAPC200X125X155]
C40  1UF  [CAPC100X50X60]
C41  1UF  [CAPC100X50X60]
C42  10UF  [CAPC200X125X155]
C43  1UF  [CAPC100X50X60]
J52  JSO_0415_01_PRESS_FIT  [JSO_0415_01_PRESS_FIT]
J53  JSO_0415_01_PRESS_FIT  [JSO_0415_01_PRESS_FIT]
J55  LPAM-50-01.0-L-08-2-K-TR  [SAMTEC_LPAM_50_030_L_08_2_K_TR]  (sections A,B,C,D,E,F,G,H)

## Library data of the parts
C1-C24 C44-C51 = CAP_NP: Cap Cer 100nF 10% 10V X7S 0201; ALT_SYMBOLS: CAPC60X30X40RND,0201_BGA; Agile Part Number: CAP-00253-01; Barcode: 100334; CIP Link: http://xsjbrdwin1/CIP-E/Component/Index/All?pn=100334; Dielectric Type: X7S; Part Type: CERAMIC; Tolerance: 10%; Voltage: 10V
J1-J18 J25-J42 J58-J69 = SMA-SCREW-ON: Conn RF 3.5mm Female Vert 50R 34GHz SMT with 2 Hole Flange; ALT_SYMBOLS: 32K10K_400_3M_73251_DUAL; Agile Part Number: CON-00346-01; Barcode: 40000066; CIP Link: http://xsjbrdwin1/CIP-E/Component/Index/All?pn=40000066; Part Type: SMA
MH1-MH4 = HOLE: MOUNTING HOLE, 150 HOLE 250 PAD; ASSEMBLY_OPTIONS: DNP; Barcode: 96000012; CIP Link: http://xsjbrdwin1/CIP-E/Component/Index/All?pn=96000012
MRB1 MRB2 = RUBBER_BUMPER: RUBBER BUMPER; Agile Part Number: MEC-00004-01; Barcode: 900001; CIP Link: http://xsjbrdwin1/CIP-E/Component/Index/All?pn=900001; MANF: KEYSTONE; MANF_P/N: 720; OWNER: 4001; Part Type: BUMPER; PartType: BUMPER; ROHS: 1; Datasheet: \\XSJ-SMB\AFX\AFX\BOARD_PROJECTS\LIBRARY\DATASHEETS\MECHANICAL\M55P121.PDF
MS1 = MECH_SCREW: 4-40 MACHINE SCREW 0.25"; Agile Part Number: MEC-00014-01; Barcode: 900005; CIP Link: http://xsjbrdwin1/CIP-E/Component/Index/All?pn=900005; MANF: OLANDER; MANF_P/N: 4C25PPMZR; OWNER: 4001; Part Type: SCREW; PartType: SCREW; ROHS: 0
MS2-MS4 = MECH_SCREW: #4-40 MACHINE SCREW 0.25"; Agile Part Number: MEC-00014-01; Barcode: 900005; CIP Link: http://xsjbrdwin1/CIP-E/Component/Index/All?pn=900005; MANF: OLANDER; MANF_P/N: 4C25PPMZR; OWNER: 4001; Part Type: SCREW; PartType: SCREW; ROHS: 0
MSO1 MSO2 = STANDOFF: #4-40 0.625" ALUM STANDOFF; Barcode: 900038; DEVICE: STANDOFF_1894; MANF: KEYSTONE; MANF_P/N: 1894; OWNER: 4001; ROHS: 1; Datasheet: \\XSJ-SMB\AFX\AFX\BOARD_PROJECTS\LIBRARY\DATASHEETS\MECHANICAL\M55-PROD31.PDF
MW1 MW2 = WASHER_FLAT_4: M4 F/W STL ZN CR3 DIN125A; Agile Part Number: MEC-00005-01; Barcode: 900082; CIP Link: http://xsjbrdwin1/CIP-E/Component/Index/All?pn=900082; MANF: OLANDER; MANF_P/N: 4NFLWZR; OWNER: 3709; Part Type: WASHER; PartType: WASHER; ROHS: 0
RFCAGE1-RFCAGE16 = MECH_RF_CAGE_25X75: Shield EMI 10.16x10.16x5.08mm TH; Agile Part Number: MEC-00151-01; Barcode: 90000030; CIP Link: http://xsjbrdwin1/CIP-E/Component/Index/All?pn=90000030; Part Type: Mechanical Part
U1 U3 U7 U9 = BD1631J50100AHF: Xfmr Balun 1.6-3.1GHz 50-100R 0805; Agile Part Number: XFR-00003-01; Barcode: 300189; CIP Link: http://xsjbrdwin1/CIP-E/Component/Index/All?pn=300189; MANF: ANAREN; OWNER: 14716; PRICE: 0.72; Part Type: BALUN; PartType: BALUN; ROHS: YES; Datasheet: \\XSJ-SMB\AFX\AFX\BOARD_PROJECTS\LIBRARY\DATASHEETS\TRANSFORMER\BD1631J50100AHF_DataSheet_RevB.pdf
U2 U4 U8 U10 = BD3150N50100AHF: Xfmr Balun 3.1-5GHz 50-100R 0404; Agile Part Number: XFR-00006-01; Barcode: 500723; CIP Link: http://xsjbrdwin1/CIP-E/Component/Index/All?pn=500723; Part Type: BALUN
U5 U6 U11 U12 = TCM2-33WX+: Xfmr RF 10-3000MHz 50R SMT; Agile Part Number: XFR-00005-01; Barcode: 300191; CIP Link: http://xsjbrdwin1/CIP-E/Component/Index/All?pn=300191; MANF: MINI-CIRCUITS; OWNER: 14716; Part Type: RF TRANSFORMER; PartType: RF TRANSFORMER; ROHS: YES; Datasheet: \\XSJ-SMB\AFX\AFX\BOARD_PROJECTS\LIBRARY\DATASHEETS\TRANSFORMER\TCM2-33WX+.pdf
U13-U16 = BD60120N50100AHF: BALUN 5.9GHZ-11.7GHZ 50/100 0404; Agile Part Number: XFR-00007-01; Barcode: 500724; CIP Link: http://xsjbrdwin1/CIP-E/Component/Index/All?pn=500724; Part Type: BALUN
J21 J23 J44 J48 = HDR_2X12: Conn Hdr Male Vert 24 Pos 2x12 2.54mm P Black TH; Agile Part Number: CON-00082-01; Barcode: 390212; CIP Link: http://xsjbrdwin1/CIP-E/Component/Index/All?pn=390212; MANF: SULLINS; MANF_P/N: PBC12DAAN; OWNER: 4001; PRICE: 0.42; Part Type: HEADER; PartType: HEADER; Pins: 24PINS; Pitch: 0.100; ROHS: Yes; Datasheet: \\XSJ-SMB\AFX\AFX\BOARD_PROJECTS\LIBRARY\\DATASHEETS\CONNECTOR\SULLINSHEADER_X2_STR.PDF
J56 J57 JHC1-JHC8 = COREHC2_8CH: CoreHC2 Cable SMD 1x8 Footprint Only; ASSEMBLY_OPTIONS: DNP; Barcode: 40000023; CIP Link: http://xsjbrdwin1/CIP-E/Component/Index/All?pn=40000023; Part Type: CONNECTOR
MN1-MN20 = MECH_NUT_4-40: CoreHC2 Cable Nut Press Fit .156 56mil; Agile Part Number: MEC-00116-01; Barcode: 90000012; CIP Link: http://xsjbrdwin1/CIP-E/Component/Index/All?pn=90000012; Part Type: Mechanical Part
C25 C36 = CAP_NP: Cap Cer 10uF 10% 25V X5R 1210; ALT_SYMBOLS: CAPC320X250X220RND; Agile Part Number: CAP-00113-01; CIP Link: http://xsjbrdwin1/CIP-E/Component/Index/All?pn=100123; Dielectric: X5R; Dielectric Type: X5R; MANF: MURATA; MANF_P/N: GRM32DR61E106KA12L; OWNER: 3709; PRICE: 0.18; Part Type: CERAMIC; PartType: CERAMIC; ROHS: Yes; Tolerance: 10%; Voltage: 25V; barcode: 100123; Datasheet: \\XSJ-SMB\AFX\AFX\BOARD_PROJECTS\LIBRARY\\DATASHEETS\CAPACITOR\GRM32DR61E106KA12L.pdf
C26 C27 C30 C31 C33 C35 C37 C38 C40 C41 C43 = CAP_NP: Cap Cer 1uF 10% 35V X5R 0402; ALT_SYMBOLS: CAPC100X50X60RND; Agile Part Number: CAP-00165-01; CIP Link: http://xsjbrdwin1/CIP-E/Component/Index/All?pn=100192; Dielectric: X5R; Dielectric Type: X5R; MANF: MURATA; MANF_P/N: GRM155R6YA105KE11D; OWNER: 3709; PRICE: 0.04; Part Type: CERAMIC; PartType: CERAMIC; ROHS: Yes; Tolerance: 10%; Voltage: 35V; barcode: 100192; Datasheet: \\XSJ-SMB\AFX\AFX\BOARD_PROJECTS\LIBRARY\DATASHEETS\CAPACITOR\GRM155R6YA105KE11D.pdf
C29 C32 C34 C39 C42 = CAP_NP: CAP CER 10UF 10V X5R 0805; ALT_SYMBOLS: CAPC200X125X155RND; Agile Part Number: CAP-00056-01; CIP Link: http://xsjbrdwin1/CIP-E/Component/Index/All?pn=100024; Dielectric: X5R; Dielectric Type: X5R; MANF: MURATA; MANF_P/N: GRM21BR61A106KE19L; OWNER: 3670; PRICE: 0.04; Part Type: CERAMIC; PartType: CERAMIC; ROHS: Yes; Tolerance: 10%; Voltage: 10V; barcode: 100024; Datasheet: \\XSJ-SMB\AFX\AFX\BOARD_PROJECTS\LIBRARY\\DATASHEETS\CAPACITOR\MURATA_GRM21BR61A106KE19L.pdf
J49 J55 = LPAM-50-01.0-L-08-2-K-TR: Conn Rcpt  Male Vert 400 Pos 8x50 1.27mm P Black SMT; Agile Part Number: CON-00316-01; Barcode: 40000031; CIP Link: http://xsjbrdwin1/CIP-E/Component/Index/All?pn=40000031; Part Type: CONNECTOR
J50-J53 = HOLE_JSO: JSO-0415-01 PRESS FIT HOLE; ASSEMBLY_OPTIONS: DNP; Barcode: 96000009; CIP Link: http://xsjbrdwin1/CIP-E/Component/Index/All?pn=96000009; Part Type: HOLE

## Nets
GND: C25.2 C26.2 C27.2 C29.2 C30.2 C31.2 C32.2 C33.2 C34.2 C35.2 C36.2 C37.2 C38.2 C39.2 C40.2 C41.2 C42.2 C43.2 J1.2 J1.3 J2.2 J2.3 J3.2 J3.3 J4.2 J4.3 J5.2 J5.3 J6.2 J6.3 J7.2 J7.3 J8.2 J8.3 J9.2 J9.3 J10.2 J10.3 J11.2 J11.3 J12.2 J12.3 J13.2 J13.3 J14.2 J14.3 J15.2 J15.3 J16.2 J16.3 J17.2 J17.3 J18.2 J18.3 J21.2(P2) J21.5(P5) J21.8(P8) J21.11(P11) J21.14(P14) J21.17(P17) J21.20(P20) J21.23(P23) J23.2(P2) J23.14(P14) J23.16(P16) J23.17(P17) J23.18(P18) J23.19(P19) J23.20(P20) J25.2 J25.3 J26.2 J26.3 J27.2 J27.3 J28.2 J28.3 J29.2 J29.3 J30.2 J30.3 J31.2 J31.3 J32.2 J32.3 J33.2 J33.3 J34.2 J34.3 J35.2 J35.3 J36.2 J36.3 J37.2 J37.3 J38.2 J38.3 J39.2 J39.3 J40.2 J40.3 J41.2 J41.3 J42.2 J42.3 J44.2(P2) J44.5(P5) J44.8(P8) J44.11(P11) J44.14(P14) J44.17(P17) J44.20(P20) J44.23(P23) J48.2(P2) J48.5(P5) J48.7(P7) J48.8(P8) J48.10(P10) J48.13(P13) J48.15(P15) J48.16(P16) J48.18(P18) J48.20(P20) J48.21(P21) J48.23(P23) J49.A1(1) J49.A2(2) J49.A3(3) J49.A4(4) J49.A5(5) J49.A6(6) J49.A7(7) J49.A8(8) J49.A9(9) J49.A10(10) J49.A11(11) J49.A12(12) J49.A13(13) J49.A14(14) J49.A15(15) J49.A16(16) J49.A17(17) J49.A18(18) J49.A19(19) J49.A20(20) J49.A21(21) J49.A22(22) J49.A23(23) J49.A24(24) J49.A25(25) J49.A26(26) J49.A27(27) J49.A28(28) J49.A29(29) J49.A30(30) J49.A31(31) J49.A32(32) J49.A33(33) J49.A34(34) J49.A35(35) J49.A36(36) J49.A37(37) J49.A38(38) J49.A39(39) J49.A40(40) J49.A41(41) J49.A42(42) J49.A44(44) J49.A46(46) J49.A48(48) J49.A50(50) J49.B1(1) J49.B3(3) J49.B4(4) J49.B5(5) J49.B6(6) J49.B8(8) J49.B9(9) J49.B10(10) J49.B11(11) J49.B13(13) J49.B14(14) J49.B15(15) J49.B16(16) J49.B18(18) J49.B19(19) J49.B20(20) J49.B21(21) J49.B23(23) J49.B24(24) J49.B25(25) J49.B26(26) J49.B28(28) J49.B29(29) J49.B30(30) J49.B31(31) J49.B33(33) J49.B34(34) J49.B35(35) J49.B36(36) J49.B38(38) J49.B39(39) J49.B40(40) J49.B41(41) J49.B43(43) J49.B45(45) J49.B47(47) J49.B49(49) J49.C1(1) J49.C3(3) J49.C4(4) J49.C5(5) J49.C6(6) J49.C8(8) J49.C9(9) J49.C10(10) J49.C11(11) J49.C13(13) J49.C14(14) J49.C15(15) J49.C16(16) J49.C18(18) J49.C19(19) J49.C20(20) J49.C21(21) J49.C23(23) J49.C24(24) J49.C25(25) J49.C26(26) J49.C28(28) J49.C29(29) J49.C30(30) J49.C31(31) J49.C33(33) J49.C34(34) J49.C35(35) J49.C36(36) J49.C38(38) J49.C39(39) J49.C40(40) J49.C41(41) J49.C42(42) J49.C44(44) J49.C46(46) J49.C48(48) J49.C50(50) J49.D1(1) J49.D2(2) J49.D3(3) J49.D4(4) J49.D5(5) J49.D6(6) J49.D7(7) J49.D8(8) J49.D9(9) J49.D10(10) J49.D11(11) J49.D12(12) J49.D13(13) J49.D14(14) J49.D15(15) J49.D16(16) J49.D17(17) J49.D18(18) J49.D19(19) J49.D20(20) J49.D21(21) J49.D22(22) J49.D23(23) J49.D24(24) J49.D25(25) J49.D26(26) J49.D27(27) J49.D28(28) J49.D29(29) J49.D30(30) J49.D31(31) J49.D32(32) J49.D33(33) J49.D34(34) J49.D35(35) J49.D36(36) J49.D37(37) J49.D38(38) J49.D39(39) J49.D40(40) J49.D41(41) J49.D43(43) J49.D45(45) J49.D47(47) J49.D49(49) J49.E1(1) J49.E2(2) J49.E3(3) J49.E4(4) J49.E5(5) J49.E6(6) J49.E7(7) J49.E8(8) J49.E9(9) J49.E10(10) J49.E11(11) J49.E12(12) J49.E13(13) J49.E14(14) J49.E15(15) J49.E16(16) J49.E17(17) J49.E18(18) J49.E19(19) J49.E20(20) J49.E21(21) J49.E22(22) J49.E23(23) J49.E24(24) J49.E25(25) J49.E26(26) J49.E27(27) J49.E28(28) J49.E29(29) J49.E30(30) J49.E31(31) J49.E32(32) J49.E33(33) J49.E34(34) J49.E35(35) J49.E36(36) J49.E37(37) J49.E38(38) J49.E39(39) J49.E40(40) J49.E41(41) J49.E42(42) J49.E44(44) J49.E46(46) J49.E48(48) J49.E50(50) J49.F1(1) J49.F2(2) J49.F3(3) J49.F4(4) J49.F6(6) J49.F7(7) J49.F8(8) J49.F9(9) J49.F11(11) J49.F12(12) J49.F13(13) J49.F14(14) J49.F16(16) J49.F17(17) J49.F18(18) J49.F19(19) J49.F21(21) J49.F22(22) J49.F23(23) J49.F24(24) J49.F26(26) J49.F27(27) J49.F28(28) J49.F29(29) J49.F31(31) J49.F32(32) J49.F33(33) J49.F34(34) J49.F36(36) J49.F37(37) J49.F38(38) J49.F39(39) J49.F41(41) J49.F43(43) J49.F45(45) J49.F47(47) J49.F49(49) J49.G1(1) J49.G2(2) J49.G3(3) J49.G4(4) J49.G6(6) J49.G7(7) J49.G8(8) J49.G9(9) J49.G11(11) J49.G12(12) J49.G13(13) J49.G14(14) J49.G16(16) J49.G17(17) J49.G18(18) J49.G19(19) J49.G21(21) J49.G22(22) J49.G23(23) J49.G24(24) J49.G26(26) J49.G27(27) J49.G28(28) J49.G29(29) J49.G31(31) J49.G32(32) J49.G33(33) J49.G34(34) J49.G36(36) J49.G37(37) J49.G38(38) J49.G39(39) J49.G41(41) J49.G42(42) J49.G44(44) J49.G46(46) J49.G48(48) J49.G50(50) J49.H1(1) J49.H2(2) J49.H3(3) J49.H4(4) J49.H5(5) J49.H6(6) J49.H7(7) J49.H8(8) J49.H9(9) J49.H10(10) J49.H11(11) J49.H12(12) J49.H13(13) J49.H14(14) J49.H15(15) J49.H16(16) J49.H17(17) J49.H18(18) J49.H19(19) J49.H20(20) J49.H21(21) J49.H22(22) J49.H23(23) J49.H24(24) J49.H25(25) J49.H26(26) J49.H27(27) J49.H28(28) J49.H29(29) J49.H30(30) J49.H31(31) J49.H32(32) J49.H33(33) J49.H34(34) J49.H35(35) J49.H36(36) J49.H37(37) J49.H38(38) J49.H39(39) J49.H40(40) J49.H41(41) J49.H43(43) J49.H45(45) J49.H47(47) J49.H49(49) J55.A1(1) J55.A3(3) J55.A5(5) J55.A7(7) J55.A9(9) J55.A10(10) J55.A11(11) J55.A12(12) J55.A13(13) J55.A14(14) J55.A15(15) J55.A16(16) J55.A17(17) J55.A18(18) J55.A19(19) J55.A20(20) J55.A21(21) J55.A22(22) J55.A23(23) J55.A24(24) J55.A25(25) J55.A26(26) J55.A27(27) J55.A28(28) J55.A29(29) J55.A30(30) J55.A31(31) J55.A32(32) J55.A33(33) J55.A34(34) J55.A35(35) J55.A36(36) J55.A37(37) J55.A38(38) J55.A39(39) J55.A40(40) J55.A41(41) J55.A42(42) J55.A43(43) J55.A44(44) J55.A45(45) J55.A46(46) J55.A47(47) J55.A48(48) J55.A49(49) J55.A50(50) J55.B2(2) J55.B4(4) J55.B6(6) J55.B8(8) J55.B10(10) J55.B12(12) J55.B13(13) J55.B14(14) J55.B15(15) J55.B17(17) J55.B18(18) J55.B19(19) J55.B20(20) J55.B22(22) J55.B23(23) J55.B24(24) J55.B25(25) J55.B27(27) J55.B28(28) J55.B29(29) J55.B30(30) J55.B32(32) J55.B33(33) J55.B34(34) J55.B35(35) J55.B37(37) J55.B38(38) J55.B39(39) J55.B40(40) J55.B42(42) J55.B43(43) J55.B44(44) J55.B45(45) J55.B47(47) J55.B48(48) J55.B49(49) J55.B50(50) J55.C1(1) J55.C3(3) J55.C5(5) J55.C7(7) J55.C9(9) J55.C10(10) J55.C12(12) J55.C13(13) J55.C14(14) J55.C15(15) J55.C17(17) J55.C18(18) J55.C19(19) J55.C20(20) J55.C22(22) J55.C23(23) J55.C24(24) J55.C25(25) J55.C27(27) J55.C28(28) J55.C29(29) J55.C30(30) J55.C32(32) J55.C33(33) J55.C34(34) J55.C35(35) J55.C37(37) J55.C38(38) J55.C39(39) J55.C40(40) J55.C42(42) J55.C43(43) J55.C44(44) J55.C45(45) J55.C47(47) J55.C48(48) J55.C49(49) J55.C50(50) J55.D2(2) J55.D4(4) J55.D6(6) J55.D8(8) J55.D10(10) J55.D11(11) J55.D12(12) J55.D13(13) J55.D14(14) J55.D15(15) J55.D16(16) J55.D17(17) J55.D18(18) J55.D19(19) J55.D20(20) J55.D21(21) J55.D22(22) J55.D23(23) J55.D24(24) J55.D25(25) J55.D26(26) J55.D27(27) J55.D28(28) J55.D29(29) J55.D30(30) J55.D31(31) J55.D32(32) J55.D33(33) J55.D34(34) J55.D35(35) J55.D36(36) J55.D37(37) J55.D38(38) J55.D39(39) J55.D40(40) J55.D41(41) J55.D42(42) J55.D43(43) J55.D44(44) J55.D45(45) J55.D46(46) J55.D47(47) J55.D48(48) J55.D49(49) J55.D50(50) J55.E1(1) J55.E3(3) J55.E5(5) J55.E7(7) J55.E9(9) J55.E10(10) J55.E11(11) J55.E12(12) J55.E13(13) J55.E14(14) J55.E15(15) J55.E16(16) J55.E17(17) J55.E18(18) J55.E19(19) J55.E20(20) J55.E21(21) J55.E22(22) J55.E23(23) J55.E24(24) J55.E25(25) J55.E26(26) J55.E27(27) J55.E28(28) J55.E29(29) J55.E30(30) J55.E31(31) J55.E32(32) J55.E33(33) J55.E34(34) J55.E35(35) J55.E36(36) J55.E37(37) J55.E38(38) J55.E39(39) J55.E40(40) J55.E41(41) J55.E42(42) J55.E43(43) J55.E44(44) J55.E45(45) J55.E46(46) J55.E47(47) J55.E48(48) J55.E49(49) J55.E50(50) J55.F2(2) J55.F4(4) J55.F6(6) J55.F8(8) J55.F10(10) J55.F11(11) J55.F12(12) J55.F13(13) J55.F15(15) J55.F16(16) J55.F17(17) J55.F18(18) J55.F20(20) J55.F21(21) J55.F22(22) J55.F23(23) J55.F25(25) J55.F26(26) J55.F27(27) J55.F28(28) J55.F30(30) J55.F31(31) J55.F32(32) J55.F33(33) J55.F35(35) J55.F36(36) J55.F37(37) J55.F38(38) J55.F40(40) J55.F41(41) J55.F42(42) J55.F43(43) J55.F45(45) J55.F46(46) J55.F47(47) J55.F48(48) J55.F50(50) J55.G1(1) J55.G3(3) J55.G5(5) J55.G7(7) J55.G9(9) J55.G10(10) J55.G11(11) J55.G12(12) J55.G13(13) J55.G15(15) J55.G16(16) J55.G17(17) J55.G18(18) J55.G20(20) J55.G21(21) J55.G22(22) J55.G23(23) J55.G25(25) J55.G26(26) J55.G27(27) J55.G28(28) J55.G30(30) J55.G31(31) J55.G32(32) J55.G33(33) J55.G35(35) J55.G36(36) J55.G37(37) J55.G38(38) J55.G40(40) J55.G41(41) J55.G42(42) J55.G43(43) J55.G45(45) J55.G46(46) J55.G47(47) J55.G48(48) J55.G50(50) J55.H2(2) J55.H4(4) J55.H6(6) J55.H8(8) J55.H10(10) J55.H11(11) J55.H12(12) J55.H13(13) J55.H14(14) J55.H15(15) J55.H16(16) J55.H17(17) J55.H18(18) J55.H19(19) J55.H20(20) J55.H21(21) J55.H22(22) J55.H23(23) J55.H24(24) J55.H25(25) J55.H26(26) J55.H27(27) J55.H28(28) J55.H29(29) J55.H30(30) J55.H31(31) J55.H32(32) J55.H33(33) J55.H34(34) J55.H35(35) J55.H36(36) J55.H37(37) J55.H38(38) J55.H39(39) J55.H40(40) J55.H41(41) J55.H42(42) J55.H43(43) J55.H44(44) J55.H45(45) J55.H46(46) J55.H47(47) J55.H48(48) J55.H49(49) J55.H50(50) J56.9(GND1) J56.10(GND2) J57.9(GND1) J57.10(GND2) J58.2 J58.3 J59.2 J59.3 J60.2 J60.3 J61.2 J61.3 J62.2 J62.3 J63.2 J63.3 J64.2 J64.3 J65.2 J65.3 J66.2 J66.3 J67.2 J67.3 J68.2 J68.3 J69.2 J69.3 JHC1.9(GND1) JHC1.10(GND2) JHC2.9(GND1) JHC2.10(GND2) JHC3.9(GND1) JHC3.10(GND2) JHC4.9(GND1) JHC4.10(GND2) JHC5.9(GND1) JHC5.10(GND2) JHC6.9(GND1) JHC6.10(GND2) JHC7.9(GND1) JHC7.10(GND2) JHC8.9(GND1) JHC8.10(GND2) RFCAGE1.1(GND1) RFCAGE1.2(GND2) RFCAGE1.3(GND3) RFCAGE1.4(GND4) RFCAGE2.1(GND1) RFCAGE2.2(GND2) RFCAGE2.3(GND3) RFCAGE2.4(GND4) RFCAGE3.1(GND1) RFCAGE3.2(GND2) RFCAGE3.3(GND3) RFCAGE3.4(GND4) RFCAGE4.1(GND1) RFCAGE4.2(GND2) RFCAGE4.3(GND3) RFCAGE4.4(GND4) RFCAGE5.1(GND1) RFCAGE5.2(GND2) RFCAGE5.3(GND3) RFCAGE5.4(GND4) RFCAGE6.1(GND1) RFCAGE6.2(GND2) RFCAGE6.3(GND3) RFCAGE6.4(GND4) RFCAGE7.1(GND1) RFCAGE7.2(GND2) RFCAGE7.3(GND3) RFCAGE7.4(GND4) RFCAGE8.1(GND1) RFCAGE8.2(GND2) RFCAGE8.3(GND3) RFCAGE8.4(GND4) RFCAGE9.1(GND1) RFCAGE9.2(GND2) RFCAGE9.3(GND3) RFCAGE9.4(GND4) RFCAGE10.1(GND1) RFCAGE10.2(GND2) RFCAGE10.3(GND3) RFCAGE10.4(GND4) RFCAGE11.1(GND1) RFCAGE11.2(GND2) RFCAGE11.3(GND3) RFCAGE11.4(GND4) RFCAGE12.1(GND1) RFCAGE12.2(GND2) RFCAGE12.3(GND3) RFCAGE12.4(GND4) RFCAGE13.1(GND1) RFCAGE13.2(GND2) RFCAGE13.3(GND3) RFCAGE13.4(GND4) RFCAGE14.1(GND1) RFCAGE14.2(GND2) RFCAGE14.3(GND3) RFCAGE14.4(GND4) RFCAGE15.1(GND1) RFCAGE15.2(GND2) RFCAGE15.3(GND3) RFCAGE15.4(GND4) RFCAGE16.1(GND1) RFCAGE16.2(GND2) RFCAGE16.3(GND3) RFCAGE16.4(GND4) U1.2(GND) U1.5(GND) U2.1(GND) U3.2(GND) U3.5(GND) U4.1(GND) U5.2(GND) U5.5(GND) U6.2(GND) U6.5(GND) U7.2(GND) U7.5(GND) U8.1(GND) U9.2(GND) U9.5(GND) U10.1(GND) U11.2(GND) U11.5(GND) U12.2(GND) U12.5(GND) U13.1(GND) U14.1(GND) U15.1(GND) U16.1(GND)
VCC12_SW: C25.1 C26.1 C27.1 C36.1 C37.1 C38.1 J48.22(P22) J48.24(P24) J55.A6(6) J55.B7(7) J55.C6(6) J55.D7(7) J55.E6(6) J55.F7(7) J55.G6(6) J55.H7(7)
ADC224_T0_CH0_N: J49.F40(40) JHC5.2(P2)
ADC224_T0_CH0_P: J49.G40(40) JHC5.1(P1)
ADC224_T0_CH1_N: J49.B37(37) JHC6.2(P2)
ADC224_T0_CH1_P: J49.C37(37) JHC6.1(P1)
ADC224_T0_CH2_N: J49.F35(35) JHC5.4(P4)
ADC224_T0_CH2_P: J49.G35(35) JHC5.3(P3)
ADC224_T0_CH3_N: J49.B32(32) JHC6.4(P4)
ADC224_T0_CH3_P: J49.C32(32) JHC6.3(P3)
ADC225_T1_CH0_N: J49.F30(30) JHC5.6(P6)
ADC225_T1_CH0_P: J49.G30(30) JHC5.5(P5)
ADC225_T1_CH1_N: J49.B27(27) JHC6.6(P6)
ADC225_T1_CH1_P: J49.C27(27) JHC6.5(P5)
ADC225_T1_CH2_N: J49.F25(25) JHC5.8(P8)
ADC225_T1_CH2_P: J49.G25(25) JHC5.7(P7)
ADC225_T1_CH3_N: J49.B22(22) JHC6.8(P8)
ADC225_T1_CH3_P: J49.C22(22) JHC6.7(P7)
ADC226_T2_CH0_N: J49.F20(20) JHC7.2(P2)
ADC226_T2_CH0_P: J49.G20(20) JHC7.1(P1)
ADC226_T2_CH1_N: J49.B17(17) JHC8.2(P2)
ADC226_T2_CH1_P: J49.C17(17) JHC8.1(P1)
ADC226_T2_CH2_N: J49.F15(15) JHC7.4(P4)
ADC226_T2_CH2_P: J49.G15(15) JHC7.3(P3)
ADC226_T2_CH3_N: J49.B12(12) JHC8.4(P4)
ADC226_T2_CH3_P: J49.C12(12) JHC8.3(P3)
ADC227_T3_CH0_N: J49.F10(10) JHC7.6(P6)
ADC227_T3_CH0_P: J49.G10(10) JHC7.5(P5)
ADC227_T3_CH1_N: J49.B7(7) JHC8.6(P6)
ADC227_T3_CH1_P: J49.C7(7) JHC8.5(P5)
ADC227_T3_CH2_N: J49.F5(5) JHC7.8(P8)
ADC227_T3_CH2_P: J49.G5(5) JHC7.7(P7)
ADC227_T3_CH3_N: J49.B2(2) JHC8.8(P8)
ADC227_T3_CH3_P: J49.C2(2) JHC8.7(P7)
ADCIO_00: J21.1(P1) J49.A47(47)
ADCIO_01: J21.3(P3) J49.A49(49)
ADCIO_02: J21.7(P7) J49.B46(46)
ADCIO_03: J21.9(P9) J49.B48(48)
ADCIO_04: J21.13(P13) J49.C47(47)
ADCIO_05: J21.15(P15) J49.C49(49)
ADCIO_06: J21.19(P19) J49.D46(46)
ADCIO_07: J21.21(P21) J49.D48(48)
ADCIO_08: J23.1(P1) J49.E47(47)
ADCIO_09: J23.3(P3) J49.E49(49)
ADCIO_10: J21.4(P4) J49.F46(46)
ADCIO_11: J21.6(P6) J49.F48(48)
ADCIO_12: J21.10(P10) J49.G47(47)
ADCIO_13: J21.12(P12) J49.G49(49)
ADCIO_14: J21.16(P16) J49.H46(46)
ADCIO_15: J21.18(P18) J49.H48(48)
ADCIO_16: J21.22(P22)
ADCIO_17: J21.24(P24)
ADCIO_18: J23.4(P4)
ADCIO_19: J23.6(P6)
DAC228_T0_CH0_N: J55.F49(49) JHC1.2(P2)
DAC228_T0_CH0_P: J55.G49(49) JHC1.1(P1)
DAC228_T0_CH1_N: J55.B46(46) JHC2.2(P2)
DAC228_T0_CH1_P: J55.C46(46) JHC2.1(P1)
DAC228_T0_CH2_N: J55.F44(44) JHC1.4(P4)
DAC228_T0_CH2_P: J55.G44(44) JHC1.3(P3)
DAC228_T0_CH3_N: J55.B41(41) JHC2.4(P4)
DAC228_T0_CH3_P: J55.C41(41) JHC2.3(P3)
DAC229_T1_CH0_N: J55.F39(39) JHC1.6(P6)
DAC229_T1_CH0_P: J55.G39(39) JHC1.5(P5)
DAC229_T1_CH1_N: J55.B36(36) JHC2.6(P6)
DAC229_T1_CH1_P: J55.C36(36) JHC2.5(P5)
DAC229_T1_CH2_N: J55.F34(34) JHC1.8(P8)
DAC229_T1_CH2_P: J55.G34(34) JHC1.7(P7)
DAC229_T1_CH3_N: J55.B31(31) JHC2.8(P8)
DAC229_T1_CH3_P: J55.C31(31) JHC2.7(P7)
DAC230_T2_CH0_N: J55.F29(29) JHC3.2(P2)
DAC230_T2_CH0_P: J55.G29(29) JHC3.1(P1)
DAC230_T2_CH1_N: J55.B26(26) JHC4.2(P2)
DAC230_T2_CH1_P: J55.C26(26) JHC4.1(P1)
DAC230_T2_CH2_N: J55.F24(24) JHC3.4(P4)
DAC230_T2_CH2_P: J55.G24(24) JHC3.3(P3)
DAC230_T2_CH3_N: J55.B21(21) JHC4.4(P4)
DAC230_T2_CH3_P: J55.C21(21) JHC4.3(P3)
DAC231_T3_CH0_N: J55.F19(19) JHC3.6(P6)
DAC231_T3_CH0_P: J55.G19(19) JHC3.5(P5)
DAC231_T3_CH1_N: J55.B16(16) JHC4.6(P6)
DAC231_T3_CH1_P: J55.C16(16) JHC4.5(P5)
DAC231_T3_CH2_N: J55.F14(14) JHC3.8(P8)
DAC231_T3_CH2_P: J55.G14(14) JHC3.7(P7)
DAC231_T3_CH3_N: J55.B11(11) JHC4.8(P8)
DAC231_T3_CH3_P: J55.C11(11) JHC4.7(P7)
DAC_AVTT_BUS: C42.1 C43.1 J48.12(P12) J48.14(P14) J55.F1(1)
DACIO_00: J44.1(P1) J55.A2(2)
DACIO_01: J44.3(P3) J55.A4(4)
DACIO_02: J44.7(P7) J55.B3(3)
DACIO_03: J44.9(P9) J55.B5(5)
DACIO_04: J44.13(P13) J55.C2(2)
DACIO_05: J44.15(P15) J55.C4(4)
DACIO_06: J44.19(P19) J55.D3(3)
DACIO_07: J44.21(P21) J55.D5(5)
DACIO_08: J48.1(P1) J55.E2(2)
DACIO_09: J48.3(P3) J55.E4(4)
DACIO_10: J44.4(P4) J55.F3(3)
DACIO_11: J44.6(P6) J55.F5(5)
DACIO_12: J44.10(P10) J55.G2(2)
DACIO_13: J44.12(P12) J55.G4(4)
DACIO_14: J44.16(P16) J55.H3(3)
DACIO_15: J44.18(P18) J55.H5(5)
DACIO_16: J44.22(P22)
DACIO_17: J44.24(P24)
DACIO_18: J48.4(P4)
DACIO_19: J48.6(P6)
EAST_TC_LAYER2_6INCH_N: J57.5(P5) J57.6(P6)
EAST_TC_LAYER2_6INCH_P: J57.7(P7) J57.8(P8)
EAST_TC_LAYER4_6INCH_N: J57.1(P1) J57.2(P2)
EAST_TC_LAYER4_6INCH_P: J57.3(P3) J57.4(P4)
HBF_DAC_01_N: C16.2 J30.1
HFB_ADC_01: J4.1 U2.2(P)
HFB_ADC_01_N: C4.2 J6.1
HFB_ADC_01_P: C2.2 J2.1
HFB_ADC_02: J34.1 U10.2(P)
HFB_ADC_02_N: C20.2 J36.1
HFB_ADC_02_P: C18.2 J32.1
HFB_DAC_01: J27.1 U8.2(P)
HFB_DAC_01_P: C14.2 J28.1
HFB_DAC_02: J9.1 U4.2(P)
HFB_DAC_02_N: C8.2 J12.1
HFB_DAC_02_P: C6.2 J10.1
LFB_ADC_01: J13.1 U5.6(P+)
LFB_ADC_01_N: C10.2 J15.1
LFB_ADC_01_P: C9.2 J14.1
LFB_ADC_02: J17.1 U6.6(P+)
LFB_ADC_02_N: C12.2 J18.1
LFB_ADC_02_P: C11.2 J16.1
LFB_DAC_01_N: C22.2 J39.1
LFB_DAC_01_P: C21.2 J37.1
LFB_DAC_02_N: C24.2 J42.1
LFB_DAC_02_P: C23.2 J41.1
LMFB_DAC_01: J38.1 U11.6(P+)
LMFB_DAC_02: J40.1 U12.6(P+)
MFB_ADC_01: J3.1 U1.1(IN)
MFB_ADC_01_N: C3.2 J5.1
MFB_ADC_01_P: C1.2 J1.1
MFB_ADC_02: J7.1 U3.1(IN)
MFB_ADC_02_N: C7.2 J11.1
MFB_ADC_02_P: C5.2 J8.1
MFB_DAC_01: J25.1 U7.1(IN)
MFB_DAC_01_N: C15.2 J29.1
MFB_DAC_01_P: C13.2 J26.1
MFB_DAC_02: J33.1 U9.1(IN)
MFB_DAC_02_N: C19.2 J35.1
MFB_DAC_02_P: C17.2 J31.1
RFMC_2_0_I2C_SCL: J49.B50(50)
RFMC_2_0_I2C_SDA: J49.D50(50)
RFMCP_I2C_SCL: J23.22(P22)
RFMCP_I2C_SDA: J23.24(P24)
SHBF_DAC_01_N: C49.2 J66.1
SHFB_ADC_01: J59.1 U13.2(P)
SHFB_ADC_01_N: C45.2 J60.1
SHFB_ADC_01_P: C44.2 J58.1
SHFB_ADC_02: J62.1 U14.2(P)
SHFB_ADC_02_N: C47.2 J63.1
SHFB_ADC_02_P: C46.2 J61.1
SHFB_DAC_01: J65.1 U15.2(P)
SHFB_DAC_01_P: C48.2 J64.1
SHFB_DAC_02: J68.1 U16.2(P)
SHFB_DAC_02_N: C51.2 J69.1
SHFB_DAC_02_P: C50.2 J67.1
UTIL_3V3: C29.1 C30.1 C31.1 J23.21(P21) J23.23(P23) J49.A45(45) J49.B44(44) J49.C45(45) J49.D44(44) J49.E45(45) J49.F44(44) J49.G45(45) J49.H44(44)
UTIL_5V0: C39.1 C40.1 C41.1 J48.17(P17) J48.19(P19) J55.A8(8) J55.B9(9) J55.C8(8) J55.D9(9) J55.E8(8) J55.F9(9) J55.G8(8) J55.H9(9)
VADJ_ADC: C32.1 C33.1 J23.13(P13) J23.15(P15) J49.F50(50) J49.H50(50)
VADJ_DAC: C34.1 C35.1 J48.9(P9) J48.11(P11) J55.B1(1) J55.D1(1)
VCM01_224: J49.A43(43)
VCM01_225: J49.C43(43)
VCM01_226: J49.E43(43)
VCM01_227: J49.G43(43)
VCM23_224: J49.B42(42)
VCM23_225: J49.D42(42)
VCM23_226: J49.F42(42)
VCM23_227: J49.H42(42)
WEST_TC_LAYER2_6INCH_N: J56.5(P5) J56.8(P8)
WEST_TC_LAYER2_6INCH_P: J56.6(P6) J56.7(P7)
WEST_TC_LAYER4_6INCH_N: J56.1(P1) J56.4(P4)
WEST_TC_LAYER4_6INCH_P: J56.2(P2) J56.3(P3)
N21418030: C1.1 U1.3(Q1)
N21418037: C3.1 U1.4(Q2)
N21418063: C5.1 U3.3(Q1)
N21418070: C7.1 U3.4(Q2)
N21418125: C11.1 U6.3(S-)
N21418132: C12.1 U6.4(S+)
N22112796: C13.1 U7.3(Q1)
N22112801: C15.1 U7.4(Q2)
N22112826: C21.1 U11.3(S-)
N22112831: C22.1 U11.4(S+)
N22112883: C17.1 U9.3(Q1)
N22112888: C19.1 U9.4(Q2)
N22123695: C2.1 U2.3(Q1)
N22123781: C4.1 U2.4(Q2)
N22125258: C14.1 U8.3(Q1)
N22125344: C16.1 U8.4(Q2)
N22561101: C6.1 U4.3(Q1)
N22561181: C8.1 U4.4(Q2)
N22561975: C18.1 U10.3(Q1)
N22562055: C20.1 U10.4(Q2)
N22564284: C9.1 U5.3(S-)
N22564340: C10.1 U5.4(S+)
N22565110: C23.1 U12.3(S-)
N22565166: C24.1 U12.4(S+)
N22615481: C44.1 U13.3(Q1)
N22615525: C45.1 U13.4(Q2)
N22615638: C46.1 U14.3(Q1)
N22615682: C47.1 U14.4(Q2)
N22616561: C48.1 U15.3(Q1)
N22616605: C49.1 U15.4(Q2)
N22616718: C50.1 U16.3(Q1)
N22616762: C51.1 U16.4(Q2)

Not connected (* = marked no-connect by the designer): J23 5(P5)* 7(P7)* 8(P8)* 9(P9)* 10(P10)* 11(P11)* 12(P12)*; J50 1; J51 1; J52 1; J53 1; J55 H1(1); MH1 1; MH2 1; MH3 1; MH4 1; U1 6(NC)*; U3 6(NC)*; U5 1(NC)*; U6 1(NC)*; U7 6(NC)*; U9 6(NC)*; U11 1(NC)*; U12 1(NC)*

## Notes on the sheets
sheet 1
- HW-XM755
- RF BREAKOUT CARD
- Disclaimer:
- Xilinx is disclosing this user guide, manual, release note, schematic,
- and/or specification (the “Documentation”) to you solely for use in
- the development of designs to operate with Xilinx hardware devices.
- You may not reproduce, distribute, republish, download, display, post,
- or transmit the Documentation in any form or by any means including,
- but not limited to, electronic, mechanical, photocopying, recording,
- or otherwise, without the prior written consent of Xilinx.
- Xilinx expressly disclaims any liability arising out of your use of
- the Documentation. Xilinx reserves the right, at its sole discretion,
- to change the Documentation without notice at any time. Xilinx assumes
- no obligation to correct any errors contained in the Documentation, or
- to advise you of any corrections or updates. Xilinx expressly
- disclaims any liability in connection with technical support or
- assistance that may be provided to you in connection with the
- Documentation.
- THE DOCUMENTATION IS DISCLOSED TO YOU “AS-IS” WITH NO WARRANTY OF ANY
- KIND. XILINX MAKES NO OTHER WARRANTIES, WHETHER EXPRESS, IMPLIED, OR
- STATUTORY, REGARDING THE DOCUMENTATION, INCLUDING ANY WARRANTIES OF
- MERCHANTABILITY, FITNESS FOR A PARTICULAR PURPOSE, OR NONINFRINGEMENT
- OF THIRD-PARTY RIGHTS. IN NO EVENT WILL XILINX BE LIABLE FOR ANY
- CONSEQUENTIAL, INDIRECT, EXEMPLARY, SPECIAL, OR INCIDENTAL DAMAGES,
- INCLUDING ANY LOSS OF DATA OR LOST PROFITS, ARISING FROM YOUR USE OF
- THE DOCUMENTATION.
sheet 2
- BLOCK DIAGRAM
sheet 3
- ADC BALUN CHANNELS
- 4-5GHz Channels Anaren Balun
- 1-4GHz Channels Anaren Balun
- 50ohm Trace
- 100ohm Trace
  Differential
- 50ohm Trace
- 100ohm Trace
  Differential
- 50ohm Trace
- 100ohm Trace
  Differential
- 100ohm Trace
  Differential
- 6-12GHz Channels Anaren Balun
- 10M-1GHz Channels Minicircuit Balun
- 50ohm Trace
- 50ohm Trace
- 100ohm Trace
  Differential
- 100ohm Trace
  Differential
- 50ohm Trace
- 100ohm Trace
  Differential
- 50ohm Trace
- 100ohm Trace
  Differential
- Stand-off quantity TBD
sheet 4
- ADC BREAKOUT CHANNELS
- TEST COUPON
sheet 5
- DAC BALUN CHANNELS
- 4-5GHz Channels Anaren Balun
- 1-4GHz Channels Anaren Balun
- 50ohm Trace
- 50ohm Trace
- 100ohm Trace
  Differential
- 100ohm Trace
  Differential
- 50ohm Trace
- 100ohm Trace
  Differential
- 50ohm Trace
- 100ohm Trace
  Differential
- 6-12GHz Channels Anaren Balun
- 10M-1GHz Channels Minicircuit Balun
- 50ohm Trace
- 50ohm Trace
- 100ohm Trace
  Differential
- 100ohm Trace
  Differential
- 50ohm Trace
- 100ohm Trace
  Differential
- 50ohm Trace
sheet 6
- DAC BREAKOUT CHANNELS
- TEST COUPON
sheet 7
- RFMC+  ADC CONNECTOR
sheet 8
- RFMC+  DAC CONNECTOR
